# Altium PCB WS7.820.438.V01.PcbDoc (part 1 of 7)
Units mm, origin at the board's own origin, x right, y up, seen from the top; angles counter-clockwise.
Board outline 143.01 x 224 mm, 4 copper layers (Top Layer, G2, S3, Bottom Layer); 863 components, 638 nets, 2623 pads, 4664 vias.
Unrouted connection lines stored in the file: 16.
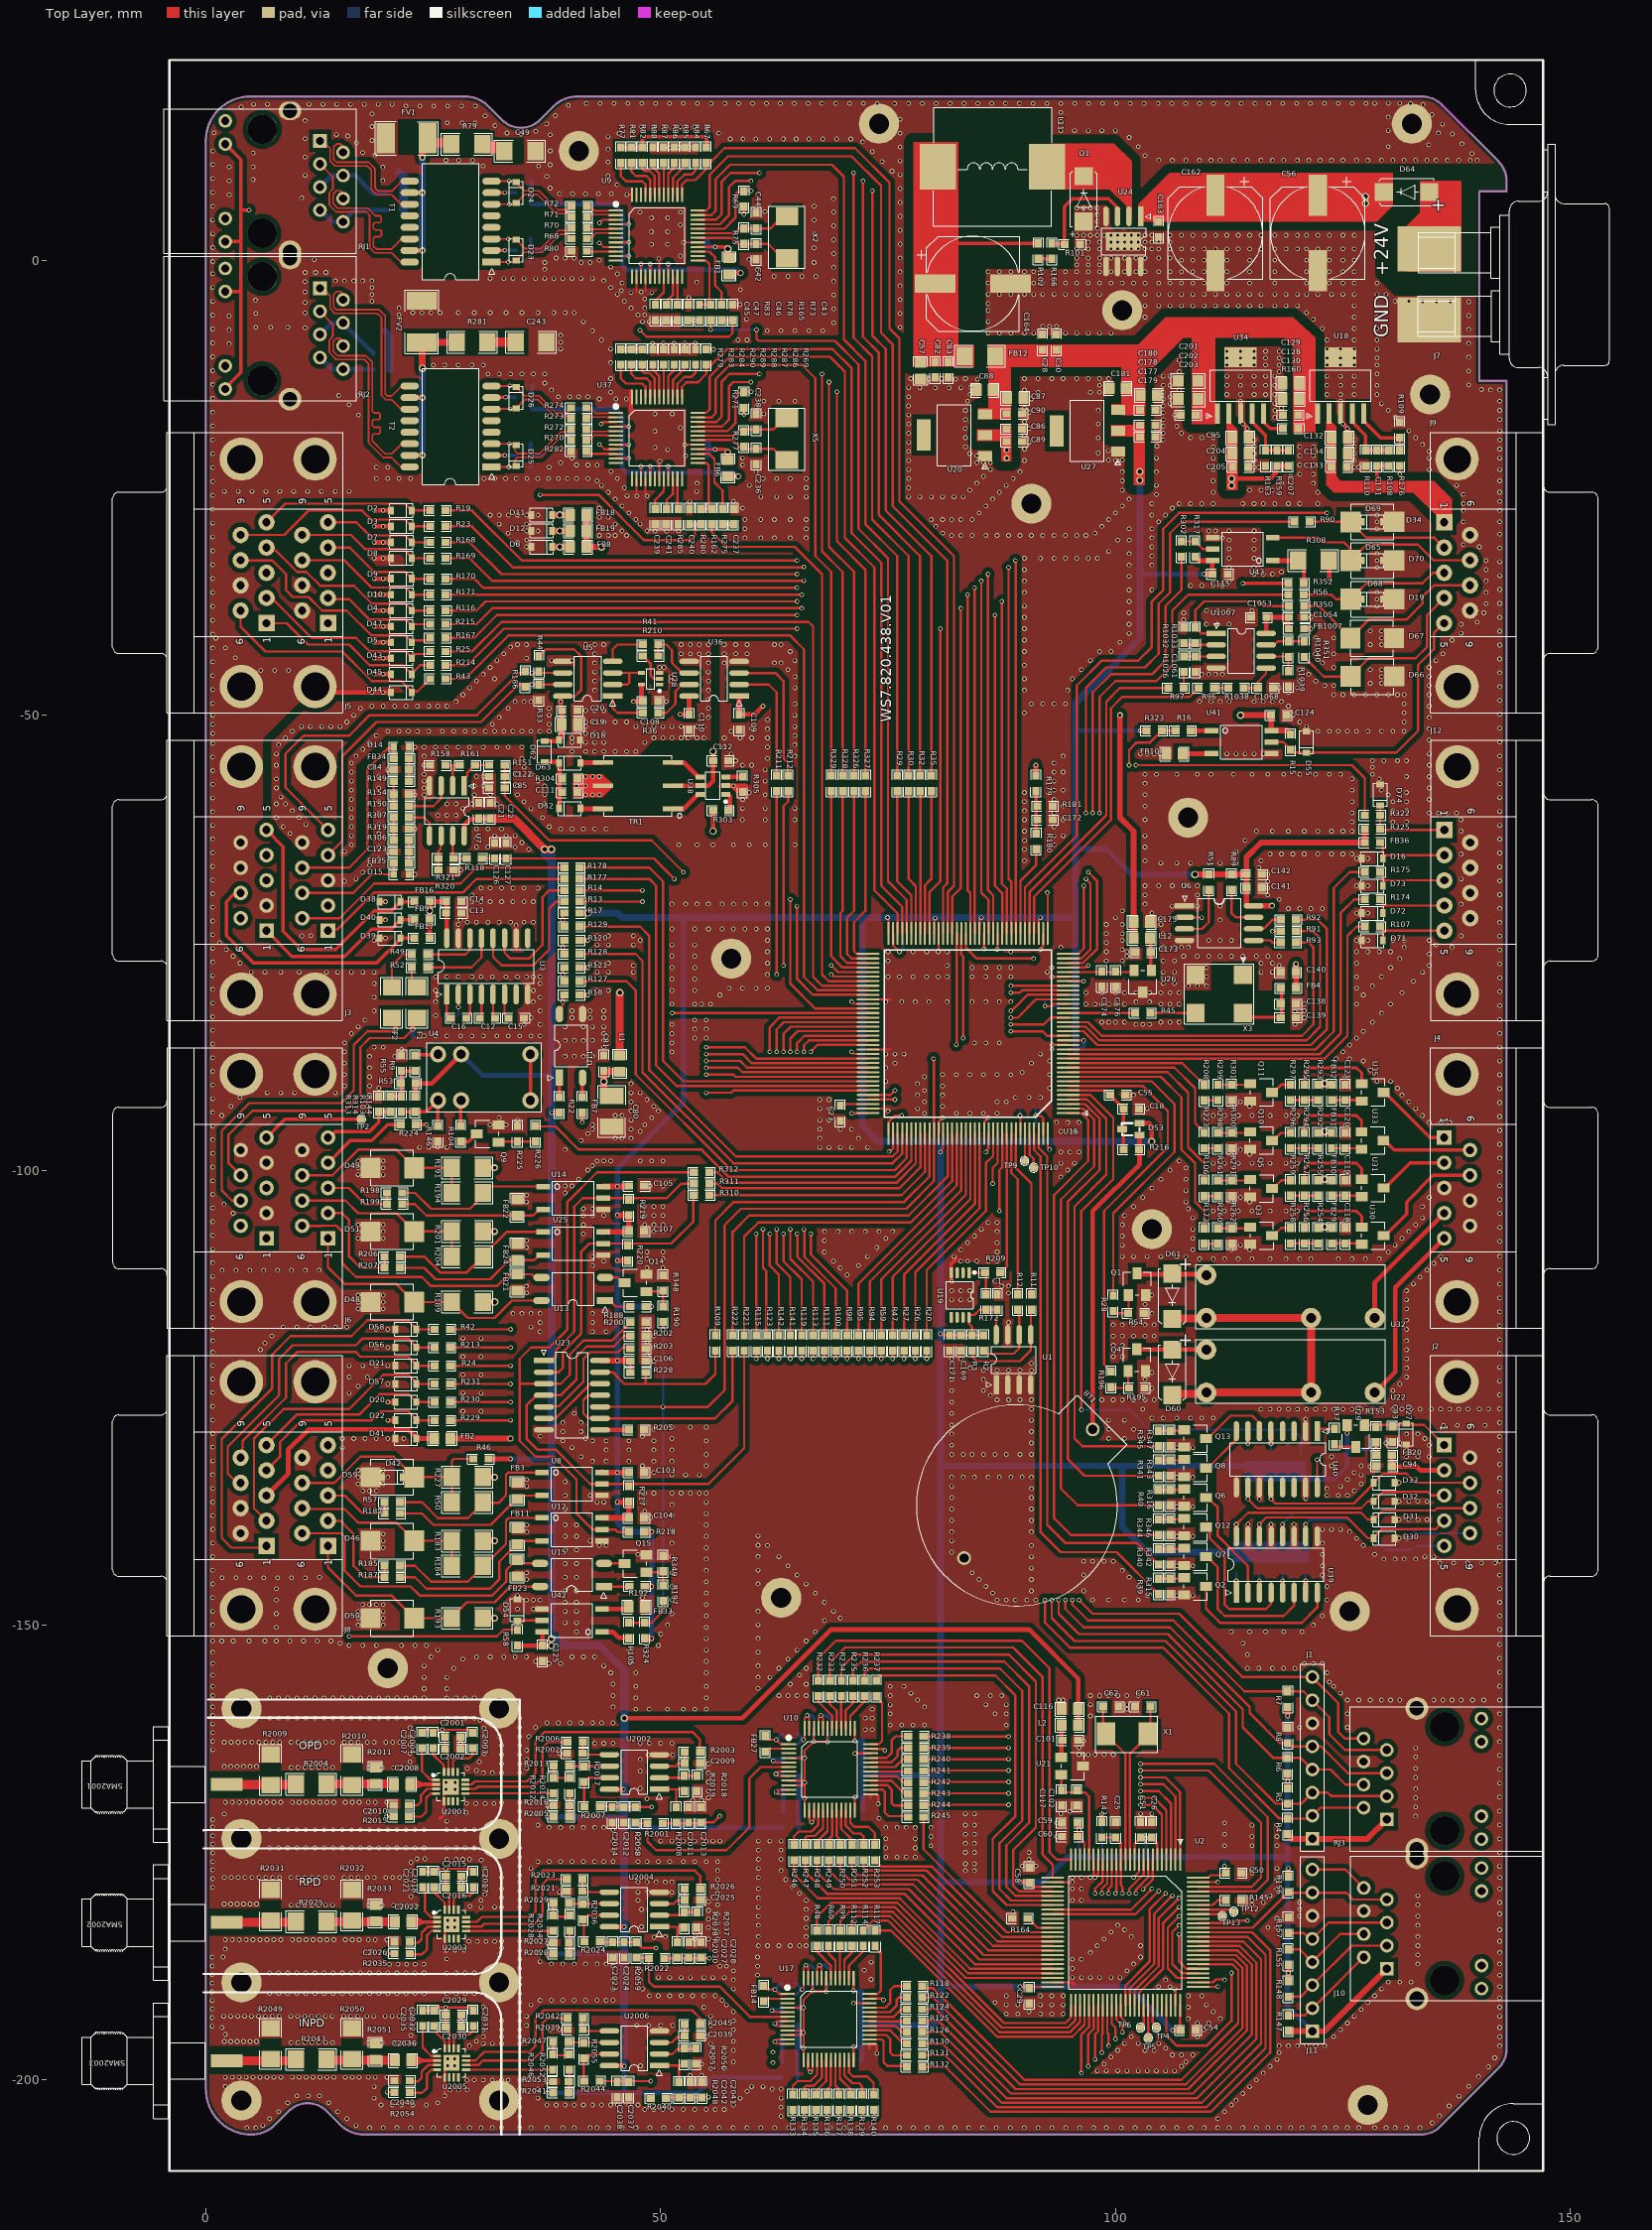
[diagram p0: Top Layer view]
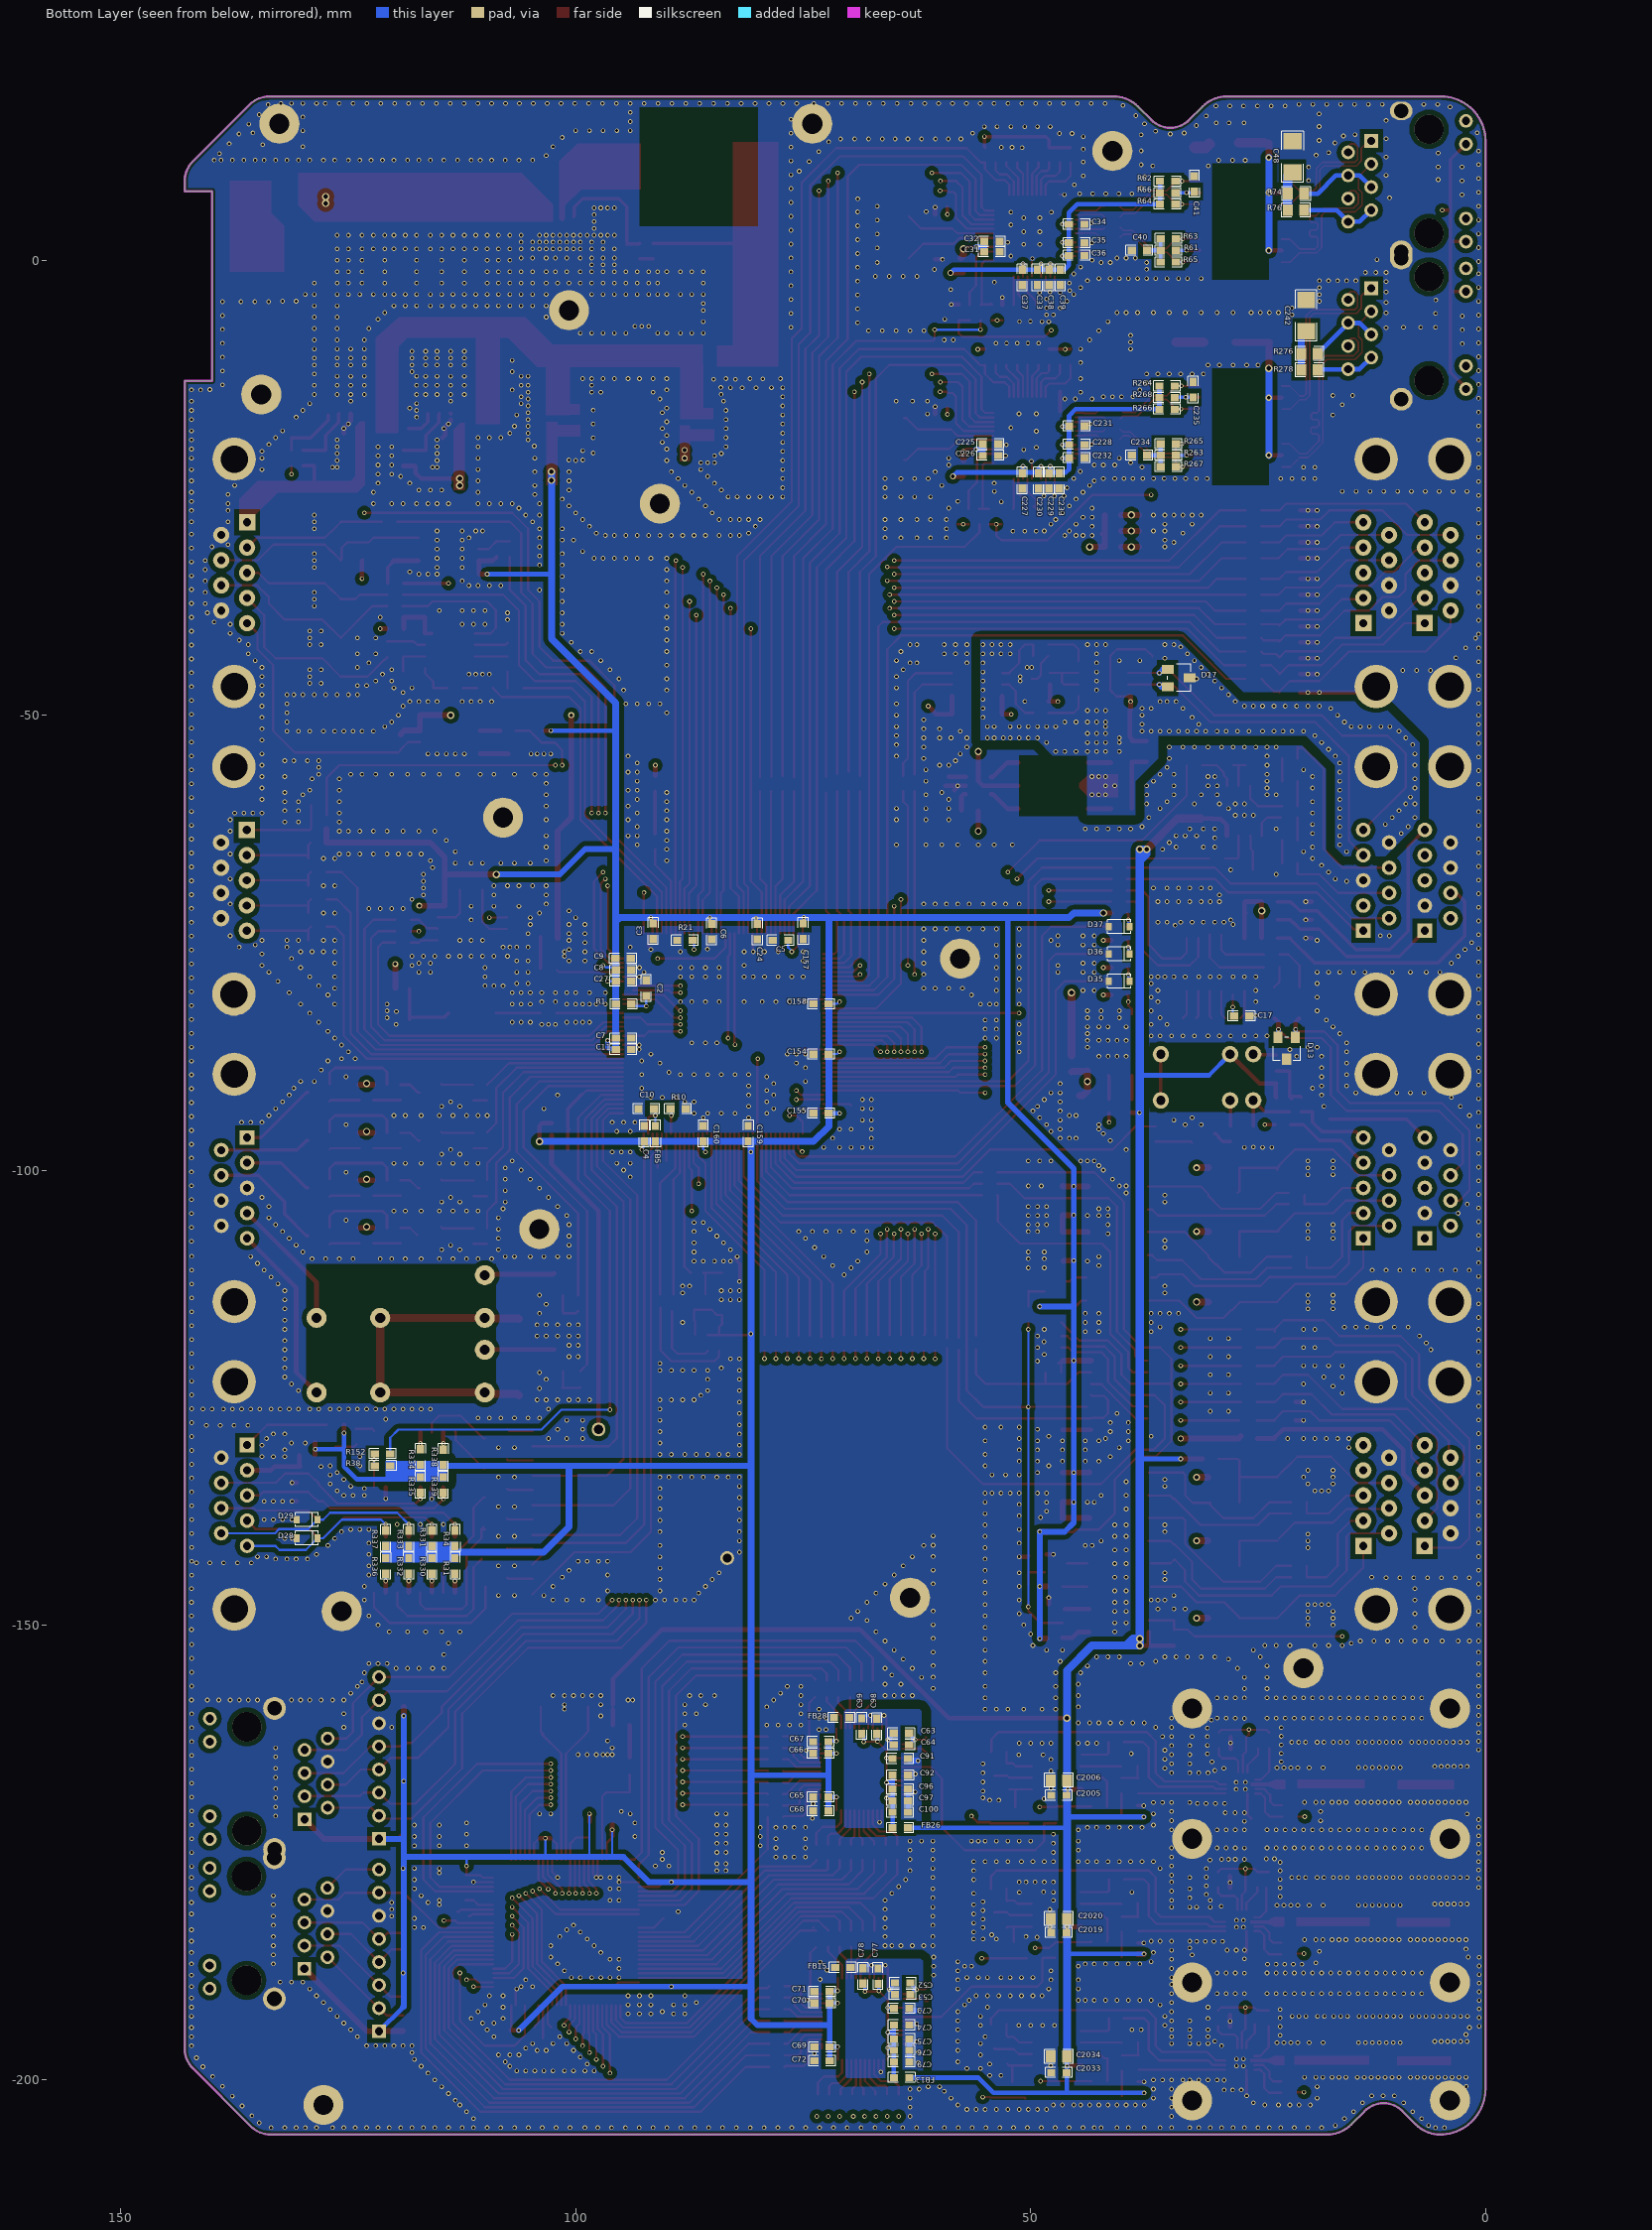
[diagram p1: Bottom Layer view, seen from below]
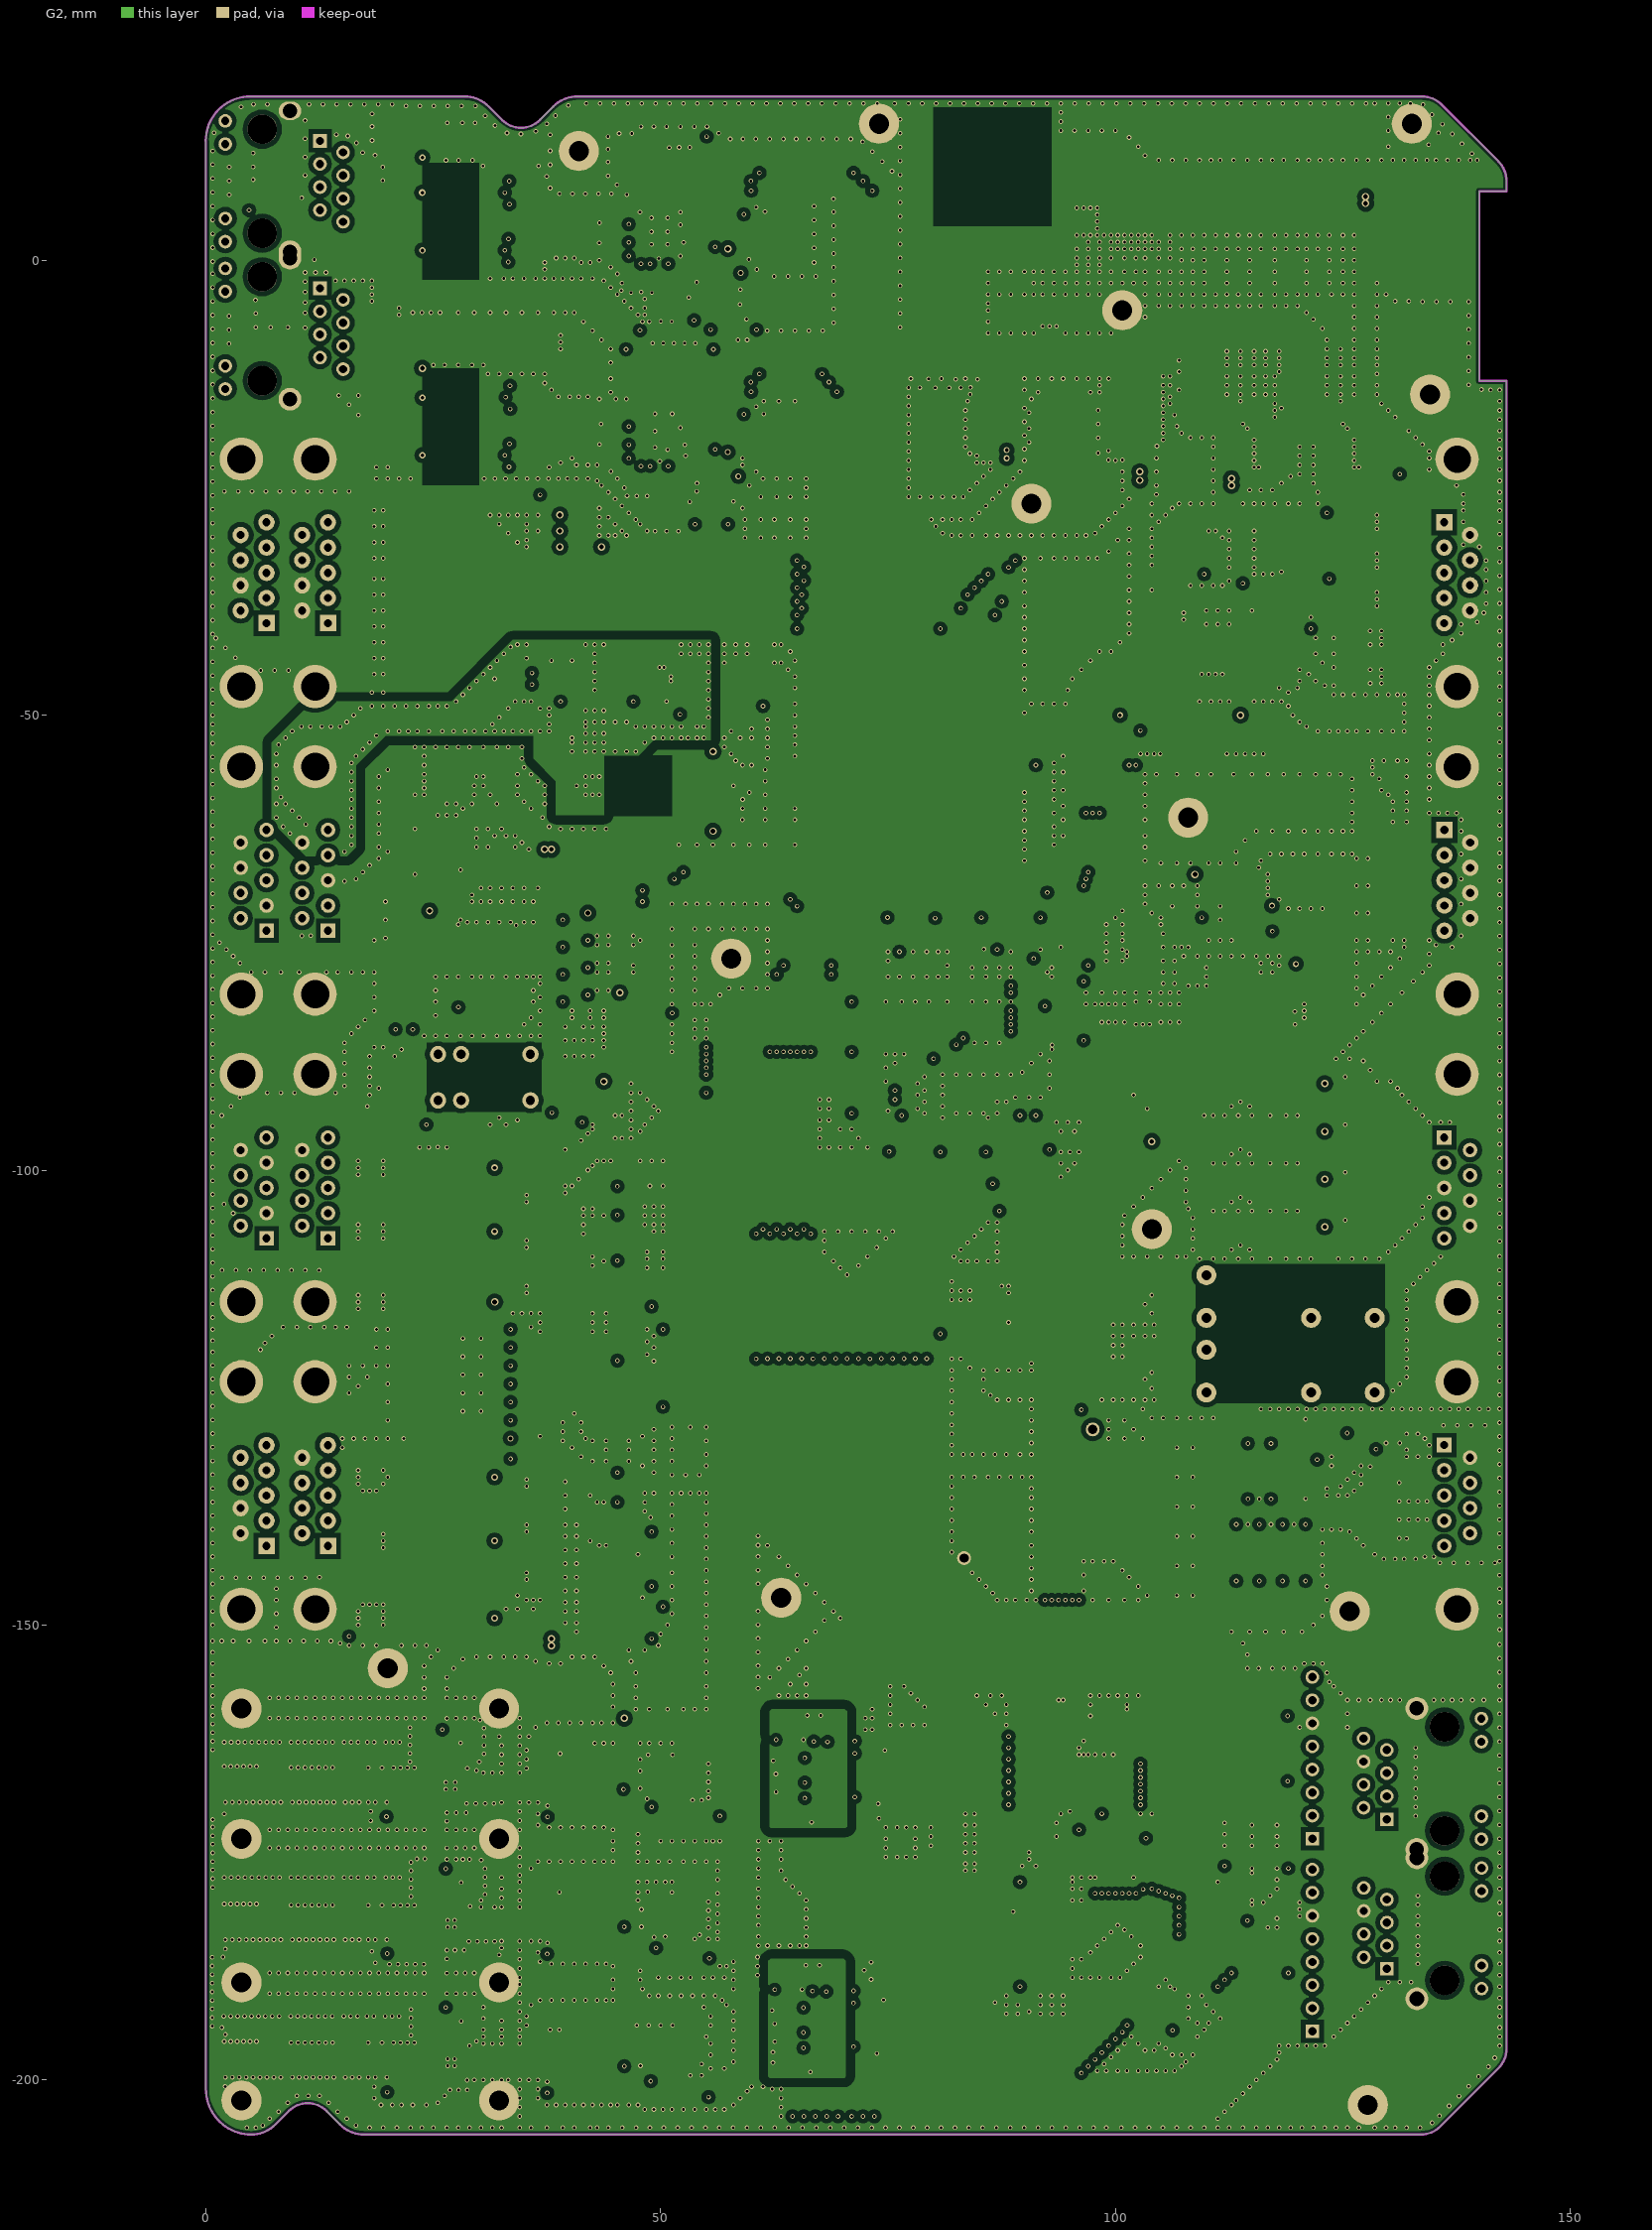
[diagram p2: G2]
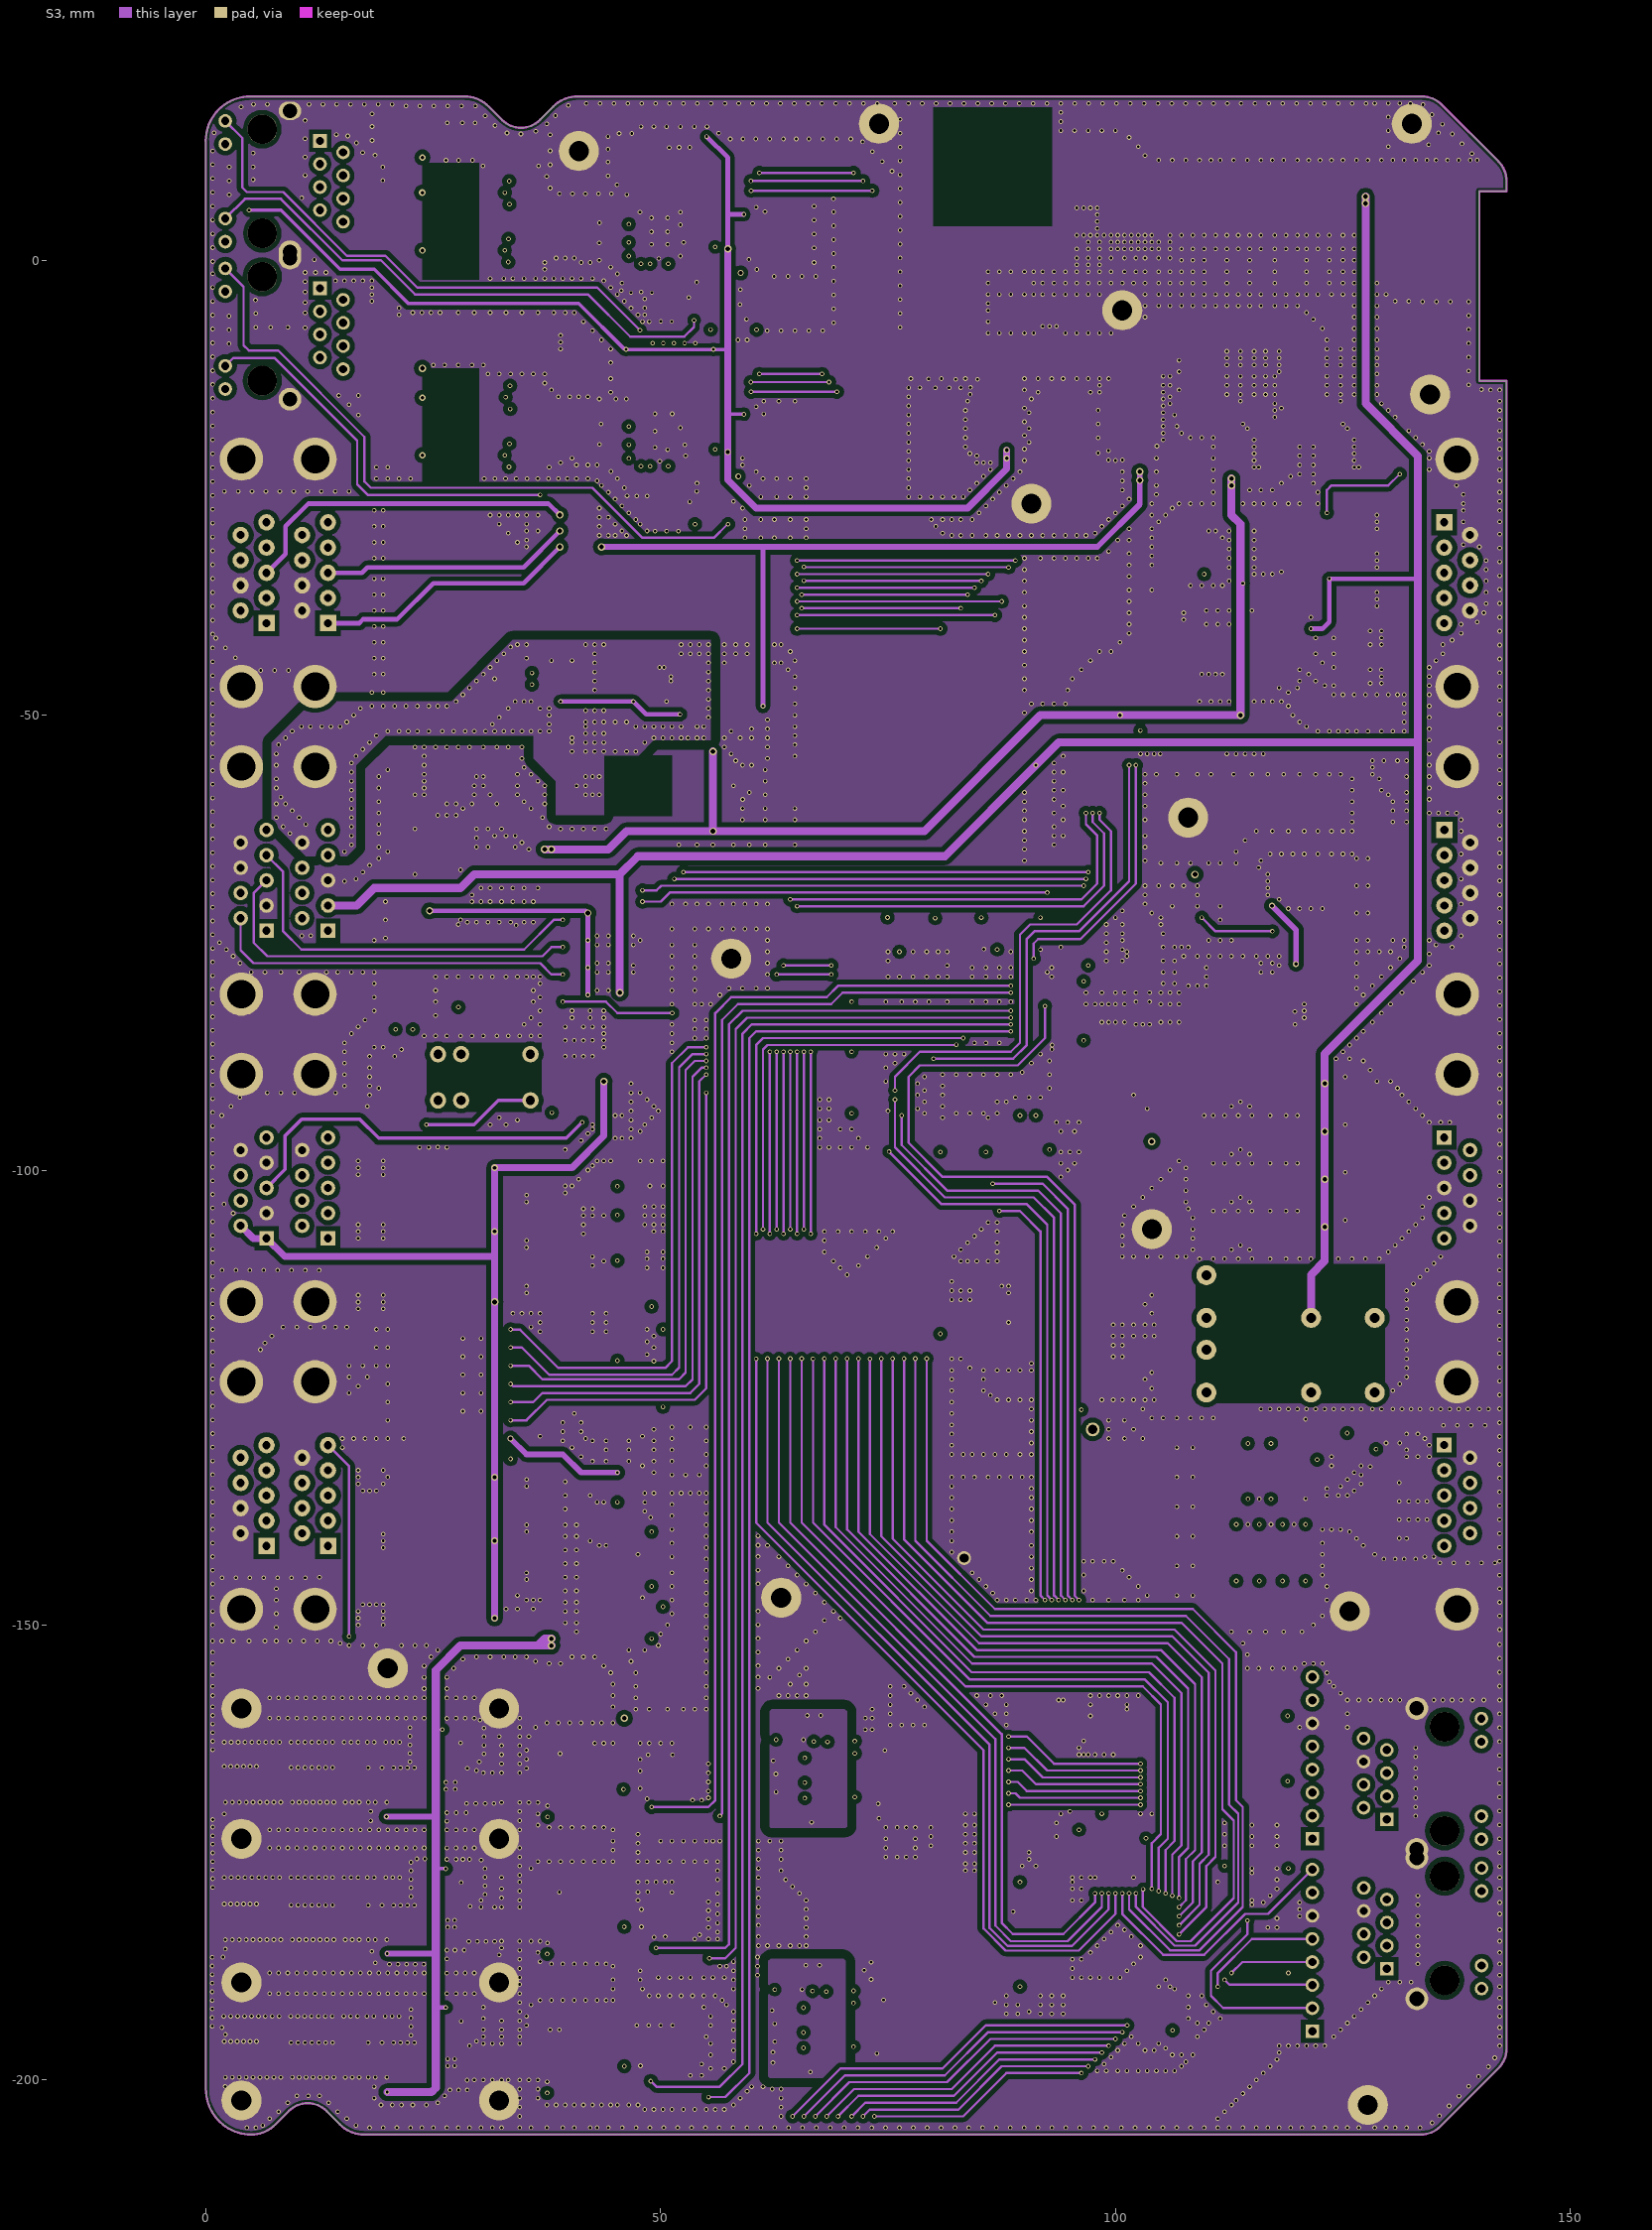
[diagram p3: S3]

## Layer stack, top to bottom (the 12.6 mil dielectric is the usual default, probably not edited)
Top Solder: solder mask 0.0102, Solder Resist, Dk 3.5
Top Layer: signal copper 0.0356
Dielectric1: core 0.32, FR-4, Dk 4.8
G2: signal copper 0.0356
Dielectric3: prepreg 0.32, FR-4, Dk 4.8
S3: signal copper 0.0356
Dielectric2: core 0.32, FR-4, Dk 4.8
Bottom Layer: signal copper 0.0356
Bottom Solder: solder mask 0.0102, Solder Resist, Dk 3.5

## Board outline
5,-206 ccw(c4.998,-202.28) 7.63,-204.909 9.113,-203.426 cw(c11.194,-205.508) 11.194,-202.564 cw(c11.194,-205.508) 13.276,-203.426 14.759,-204.909 ccw(c17.392,-202.276) 17.392,-206 133.557,-206 ccw(c133.557,-202.934) 135.725,-205.102 142.102,-198.725 ccw(c139.934,-196.557) 143,-196.557 143,-13.245 140,-13.245 140,7.583 143,7.583 143,8.697 ccw(c139.934,8.697) 142.102,10.865 135.865,17.102 ccw(c133.697,14.934) 133.697,18 40.752,18 40.843,18 ccw(c40.843,14.276) 38.21,16.909 36.727,15.426 cw(c34.646,17.508) 34.646,14.564 cw(c34.646,17.508) 32.564,15.426 31.081,16.909 ccw(c28.448,14.276) 28.448,18 4.864,18 ccw(c4.864,13.127) -0.008,13.127 0,13.127 0,-200.981 0,-201 ccw(c5,-201)

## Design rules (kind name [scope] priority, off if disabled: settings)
Clearance Clearance_4 [(OnLayer('Keep-Out Layer'))] p1: gap=0.254 ignorepadtopadclearanceinfootprint=FALSE except(0: Arc-Hole Track-Hole SMDPad-Hole THPad-Hole Via-Hole Fill-Hole Poly-Hole Region-Hole Text-Hole)
Clearance Clearance_2 [IsFill vs (InPolygon)] p2: gap=1.016 ignorepadtopadclearanceinfootprint=FALSE except(0: Arc-Hole Track-Hole SMDPad-Hole THPad-Hole Via-Hole Fill-Hole Poly-Hole Region-Hole Text-Hole)
Clearance Clearance_1 [All vs (InPolygon)] p3: gap=0.508 ignorepadtopadclearanceinfootprint=FALSE except(0: Arc-Hole Track-Hole SMDPad-Hole THPad-Hole Via-Hole Fill-Hole Poly-Hole Region-Hole Text-Hole; 1: Fill-Fill Fill-Poly Fill-Region Poly-Poly Poly-Region Region-Region)
Clearance [All] p4: gap=0.152 ignorepadtopadclearanceinfootprint=FALSE except(0: Arc-Hole Track-Hole SMDPad-Hole THPad-Hole Via-Hole Fill-Hole Poly-Hole Region-Hole Text-Hole)
ComponentClearance [All] p1: gap=0 collisioncheckmode=3 verticalgap=0 showdistances=FALSE
DiffPairsRouting DP1DiffPairsRouting [InDifferentialPair ('D01') Or InDifferentialPair ('ADC_D1011') Or InDifferentialPair ('D1213') Or InDifferentialPair ('W5500_TX2') Or InDifferentialPair ('D67') Or InDifferentialPair ('ADC_D1213') Or InDifferentialPair ('D89') Or InDifferentialPair ('TX12') Or InDifferentialPair ('D1011') Or InDifferentialPair ('ADC_DCO') Or InDifferentialPair ('ADC_D89') Or InDifferentialPair ('D23') Or InDifferentialPair ('D45') Or InDifferentialPair ('ADC_D23') Or InDifferentialPair ('ADC_D67') Or InDifferentialPair ('ADC_D01') Or InDifferentialPair ('ADC_D45') Or InDifferentialPair ('W5500_RX2') Or InDifferentialPair ('RX') Or InDifferentialPair ('RX12') Or InDifferentialPair ('W5500_RX1') Or InDifferentialPair ('TX2') Or InDifferentialPair ('TX1') Or InDifferentialPair ('RX1') Or InDifferentialPair ('RX2') Or InDifferentialPair ('TX') Or InDifferentialPair ('W5500_TX1') Or InDifferentialPair ('DAC_IOUT') Or InDifferentialPair ('OUT') Or InDifferentialPair ('DCO') Or InDifferentialPair ('ADC_CLK') Or InDifferentialPair ('VIN')] p1: maxlimit=0.508 minlimit=0.216 mostfreqgap=0.216 toplayer_minwidth=0.381 toplayer_maxwidth=0.381 toplayer_prefwidth=0.381 midlayer1_minwidth=0.381 midlayer1_maxwidth=0.381 midlayer1_prefwidth=0.381 midlayer2_minwidth=0.381 midlayer2_maxwidth=0.381 midlayer2_prefwidth=0.381 bottomlayer_minwidth=0.381 bottomlayer_maxwidth=0.381 bottomlayer_prefwidth=0.381 maxuncoupledlength=12.7
HoleSize [All] p1: absolutevalues=TRUE maxlimit=10 minlimit=0.025 maxpercent=80.000 minpercent=20.000
HoleToHoleClearance [All] p1: gap=0 allowstackedmicrovias=TRUE
MatchedLengths DP1MatchedLengths [InDifferentialPair ('D01') Or InDifferentialPair ('ADC_D1011') Or InDifferentialPair ('D1213') Or InDifferentialPair ('W5500_TX2') Or InDifferentialPair ('D67') Or InDifferentialPair ('ADC_D1213') Or InDifferentialPair ('D89') Or InDifferentialPair ('TX12') Or InDifferentialPair ('D1011') Or InDifferentialPair ('ADC_DCO') Or InDifferentialPair ('ADC_D89') Or InDifferentialPair ('D23') Or InDifferentialPair ('D45') Or InDifferentialPair ('ADC_D23') Or InDifferentialPair ('ADC_D67') Or InDifferentialPair ('ADC_D01') Or InDifferentialPair ('ADC_D45') Or InDifferentialPair ('W5500_RX2') Or InDifferentialPair ('RX') Or InDifferentialPair ('RX12') Or InDifferentialPair ('W5500_RX1') Or InDifferentialPair ('TX2') Or InDifferentialPair ('TX1') Or InDifferentialPair ('RX1') Or InDifferentialPair ('RX2') Or InDifferentialPair ('TX') Or InDifferentialPair ('W5500_TX1') Or InDifferentialPair ('DAC_IOUT') Or InDifferentialPair ('OUT') Or InDifferentialPair ('DCO') Or InDifferentialPair ('ADC_CLK') Or InDifferentialPair ('VIN')] p1 off: tolerance=5.08 checknetsindiffpair=TRUE checkdiffpairvsdiffpair=FALSE checkxsignals=FALSE checkothers=FALSE
MinimumSolderMaskSliver [All] p1: minsoldermaskwidth=0
PlaneConnect [All] p1: planeconnectstyle=Direct reliefexpansion=0.508 reliefentries=4 reliefconductorwidth=0.508 reliefairgap=0.254
PolygonConnect [All] p1: connectstyle=Direct reliefconductorwidth=0.508 reliefentries=4 polygonreliefangle="45 Angle" airgapwidth=0.254
RoutingVias [All] p1: holewidth=0.305 width=0.508 viastyle="Through Hole" minholewidth=0.305 minwidth=0.508 maxholewidth=0.711 maxwidth=1.27
SilkToSilkClearance [All] p1: silktosilkclearance=0
SilkToSolderMaskClearance SilkscreenOverComponentPads [IsPad] p1: minsilkscreentomaskgap=0 clearancetoexposedcopper=TRUE
SolderMaskExpansion [All] p1: expansion=0 istentingtop=FALSE
Width DP1Width [InDifferentialPair('D01') Or InDifferentialPair('ADC_D1011') Or InDifferentialPair('D1213') Or InDifferentialPair('W5500_TX2') Or InDifferentialPair('D67') Or InDifferentialPair('ADC_D1213') Or InDifferentialPair('D89') Or InDifferentialPair('TX12') Or InDifferentialPair('D1011') Or InDifferentialPair('ADC_DCO') Or InDifferentialPair('ADC_D89') Or InDifferentialPair('D23') Or InDifferentialPair('D45') Or InDifferentialPair('ADC_D23') Or InDifferentialPair('ADC_D67') Or InDifferentialPair('ADC_D01') Or InDifferentialPair('ADC_D45') Or InDifferentialPair('W5500_RX2') Or InDifferentialPair('RX') Or InDifferentialPair('RX12') Or InDifferentialPair('W5500_RX1') Or InDifferentialPair('TX2') Or InDifferentialPair('TX1') Or InDifferentialPair('RX1') Or InDifferentialPair('RX2') Or InDifferentialPair('TX') Or InDifferentialPair('W5500_TX1') Or InDifferentialPair('DAC_IOUT') Or InDifferentialPair('OUT') Or InDifferentialPair('DCO') Or InDifferentialPair('ADC_CLK') Or InDifferentialPair('VIN')] p1: maxlimit=0.191 minlimit=0.191 preferedwidth=0.191
Width [All] p2: maxlimit=5.08 minlimit=0.191 preferedwidth=0.191
22 further rules are at their usual default settings.

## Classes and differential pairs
component class 3-ADC: C25 C26 C29 C50 C51 C52 C53 C54 C58 C59 C60 C61 C62 C63 C64 C65 C66 C67 C68 C69 C70 C71 C72 C73 C74 C75 C76 C77 C78 C79 C91 C92 C96 C97 C98 C99 C100 C152 C153 C156 C185 C211 C256 C257 C258 C259 C260 C261 C262 C263 C264 C265 C276 C323 C324 C325 C326 C327 FB13 FB14 FB15 FB26 FB27 FB28 J10 J11 R48 R60 R99 R112 R114 R117 R118 R122 R124 R125 R126 R130 R131 R132 R133 R134 R135 R136 R137 R138 R139 R140 R143 R145 R147 R148 R155 R156 R157 R164 R232 R233 R234 R235 R236 R237 R238 R239 R240 R241 R242 R243 R244 R245 R246 R247 R248 R249 R250 R251 R252 R253 R367 R368 R369 R371 R372 R373 R374 R375 R376 R377 R378 R379 SMA3 TP4 TP5 TP6 TP12 TP13 TP? U2 U10 U17 X1
component class 5-POWER: C5? C28 C30 C56 C57 C82 C83 C86 C87 C88 C89 C90 C95 C101 C102 C116 C117 C118 C119 C120 C121 C128 C129 C130 C131 C132 C133 C134 C162 C163 C164 C172 C173 C174 C175 C176 C177 C178 C179 C180 C181 C201 C202 C203 C204 C205 C207 D1 D60 D61 D64 FB12 FB29 FB30 FB31 FB32 J7 L2 L11 L12 Q1 Q3 Q4 Q5 Q10 Q11 R28 R54 R101 R102 R108 R109 R110 R159 R160 R163 R166 R179 R180 R181 R195 R196 R254 R255 R256 R257 R258 R259 R260 R261 R262 R291 R292 R293 R294 R295 R296 R297 R298 R299 R300 R301 U18 U20 U21 U22 U24 U26 U27 U30 U31 U32 U33 U34 U35
component class 2-RJ45: C31 C32 C33 C34 C35 C36 C37 C38 C39 C40 C41 C42 C43 C44 C45 C46 C47 C48 C49 C225 C226 C227 C228 C229 C230 C231 C232 C233 C234 C235 C236 C237 C238 C239 C240 C241 C242 C243 D23 D24 D25 D26 FB1 FB6 FV1 FV2 R61 R62 R63 R64 R65 R66 R67 R68 R69 R70 R71 R72 R73 R74 R75 R76 R77 R78 R79 R80 R81 R82 R83 R84 R85 R86 R87 R88 R263 R264 R265 R266 R267 R268 R269 R270 R271 R272 R273 R274 R275 R276 R277 R278 R279 R280 R281 R282 R283 R284 R285 R286 R287 R288 R289 R290 RJ1 RJ2 T1 T2 U9 U37 X2 X5
component class 1-MCU: BT1 C1 C2 C3 C4 C5 C6 C7 C8 C9 C10 C11 C12 C13 C14 C15 C16 C17 C18 C19 C20 C21 C22 C23 C24 C27 C55 C80 C81 C84 C85 C93 C94 C103 C104 C105 C106 C107 C108 C109 C110 C111 C112 C115 C122 C123 C124 C125 C126 C127 C138 C139 C140 C141 C142 C154 C155 C157 C158 C159 C160 C169 C171 C1053 C1054 C1061 C1068 D2 D3 D4 D5 D6 D7 D8 D9 D10 D11 D12 D13 D14 D15 D16 D17 D18 D19 D20 D21 D22 D27 D28 D29 D30 D31 D32 D33 D34 D35 D36 D37 D38 D39 D40 D41 D42 D43 D44 D45 D46 D47 D48 D49 D50 D51 D52 D53 D54 D55 D56 D57 D58 D59 D62 D63 D65 D66 D67 D68 D69 D70 D71 D72 D73 D74 F1 F2 FB2 FB3 FB4 FB5 FB7 FB8 FB9 FB10 FB11 FB16 FB17 FB18 FB19 FB20 FB21 FB22 FB23 FB24 FB33 FB34 FB35 FB36 FB1007 J1 J2 J3 J4 J5 J6 J8 J9 J12 L1 Q2 Q6 Q7 Q8 Q9 Q12 Q13 Q14 Q15 R1 R2 R3 R4 R5 R6 R7 R8 R9 R10 R11 R12 R13 R14 R15 R16 R17 R18 R19 R20 R21 R22 R23 R24 R25 R26 R27 R29 R30 R31 R32 R33 R34 R35 R36 R37 R38 R39 R40 R41 R42 R43 R44 R45 R46 R47 R49 R50 R51 R52 R53 R55 R56 R57 R58 R59 R89 R90 R91 R92 R93 R94 R95 R96 R97 R98 R100 R103 R104 R105 R106 R107 R111 R113 R115 R116 R119 R120 R121 R123 R127 R128 R129 R141 R142 R144 R146 R149 R150 R151 R152 R153 R154 R158 R161 R162 R165 R167 R168 R169 R170 R171 R172 R173 R174 R175 R176 R177 R178 R182 R183 R184 R185 R186 R187 R188 R189 R190 R191 R192 R193 R194 R197 R198 R199 R200 R201 R202 R203 R204 R205 R206 R207 R208 R209 R210 R211 R212 R213 R214 R215 R216 R217 R218 R219 R220 R221 R222 R223 R224 R225 R226 R227 R228 R229 R230 R231 R302 R303 R304 R305 R306 R307 R308 R309 R310 R311 R312 R313 R314 R315 R316 R317 R318 R319 R320 R321 R322 R323 R324 R325 R326 R327 R328 R329 R330 R331 R332 R333 R334 R335 R336 R337 R338 R339 R340 R341 R342 R343 R344 R345 R346 R347 R348 R349 R350 R351 R352 R1026 R1032 R1033 R1038 R1039 R1040 RJ3 TP2 TP9 TP10 TR1 U1 U3 U4 U5 U6 U7 U8 U11 U12 U13 U14 U15 U16 U19 U23 U25 U28 U29 U36 U38 U39 U40 U41 U42 U43 U1007 X3
component class 4-RF-PD: C2001 C2002 C2003 C2004 C2005 C2006 C2007 C2008 C2009 C2010 C2011 C2012 C2013 C2014 C2015 C2016 C2017 C2018 C2019 C2020 C2021 C2022 C2023 C2024 C2025 C2026 C2027 C2028 C2029 C2030 C2031 C2032 C2033 C2034 C2035 C2036 C2037 C2038 C2039 C2040 C2041 C2042 R2001 R2002 R2003 R2004 R2005 R2006 R2007 R2008 R2009 R2010 R2011 R2012 R2013 R2014 R2015 R2016 R2017 R2018 R2019 R2020 R2021 R2022 R2023 R2024 R2025 R2026 R2027 R2028 R2029 R2030 R2031 R2032 R2033 R2034 R2035 R2036 R2037 R2038 R2039 R2040 R2041 R2042 R2043 R2044 R2045 R2046 R2047 R2048 R2049 R2050 R2051 R2052 R2053 R2054 R2055 R2056 R2057 R2058 R2059 SMA2001 SMA2002 SMA2003 U2001 U2002 U2003 U2004 U2005 U2006
differential pair W5500_TX2: +W5500_TX2_P -W5500_TX2_N
differential pair W5500_RX2: +W5500_RX2_P -W5500_RX2_N
differential pair TX12: +TX12_P -TX12_N
differential pair TX2: +TX2_P -TX2_N
differential pair RX12: +RX12_P -RX12_N
differential pair RX2: +RX2_P -RX2_N
differential pair W5500_TX1: +W5500_TX1_P -W5500_TX1_N
differential pair W5500_RX1: +W5500_RX1_P -W5500_RX1_N
differential pair TX: +TX_P -TX_N
differential pair TX1: +TX1_P -TX1_N
differential pair RX: +RX_P -RX_N
differential pair RX1: +RX1_P -RX1_N

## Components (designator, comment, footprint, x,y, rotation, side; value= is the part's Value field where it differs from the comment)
BT1 "Battery" CR2032 90.429,-135.571 r45 top locked
C1 "0.1uF" C0603#1 87,-114.5 r270 top
C2 "0.1uF" C0603#1 92.25,-80 r270 bottom
C3 "0.1uF" C0603#1 91.5,-73.75 r90 bottom
C4 "0.1uF" C0603#1 92.5,-96 r270 bottom
C5 "0.1uF" C0603#1 80.051,-73.787 r90 bottom
C6 "0.1uF" C0603#1 85.051,-73.787 r90 bottom
C7 "0.1uF" C0603#1 94.75,-85.5 r0 bottom
C8 "0.1uF" C0603#1 94.75,-78 r0 bottom
C9 "10uF/6.3V" C0603#1 94.801,-76.737 r0 bottom
C10 "0.1uF" C0603#1 92.25,-93.25 r0 bottom
C11 "10uF/6.3V" C0603#1 94.75,-86.75 r0 bottom
C12 "0.1uF" C0603#1 30.95,-83.303 r0 top
C13 "0.1uF" C0603#1 27.25,-71.75 r180 top
C14 "1uF" C0603#1 27.25,-70.5 r0 top
C15 "0.1uF" C0603#1 34.125,-83.303 r0 top
C16 "0.1uF" C0603#1 27.775,-83.303 r0 top
C17 "0.1uF" C0603#1 26.797,-83.058 r180 bottom
C18 "0.1uF" C0603#2 101.75,-93.25 r0 top
C19 "10uF/10V" C0805#1 40,-51 r180 top
C20 "0.1uF" C0603#1 40,-49.5 r180 top
C21 "0.1uF" C0603#2 30,-60.5 r90 top
C22 "2.2UF" C0603#1 31.25,-60.5 r90 top
C23 "2.2uF" C0603#2 69.75,-93.75 r270 top
C24 "2.2uF" C0603#2 77.5,-74.75 r180 bottom
C25 "0.1uF" C0603#1 100,-172.5 r270 top
C26 "0.1uF" C0603#1 104,-172.5 r270 top
C27 "0.1uF" C0603#2 94.75,-79.25 r180 bottom
C28 "1nF" C0603#2 92,-9 r90 top
C29 "0.1uF" C0603#2 90.5,-190.75 r270 top
C30 "0.1uF" C0603#2 93.5,-9 r90 top
C31 "0.1uF" C0603#1 54.252,0.917 r0 bottom
C32 "10uF/6.3V" C0603#1 54.252,2.09 r0 bottom
C33 "0.1uF" C0603#1 49.256,-1.89 r90 bottom
C34 "0.1uF" C0603#1 44.938,3.952 r0 bottom
C35 "0.1uF" C0603#1 44.938,1.92 r0 bottom
C36 "0.1uF" C0603#1 44.938,0.523 r0 bottom
C37 "0.1uF" C0603#1 50.907,-1.89 r90 bottom
C38 "0.1uF" C0603#1 47.986,-1.89 r90 bottom
C39 "10uF/6.3V" C0603#1 46.716,-1.89 r90 bottom
C40 "10nF" C0603#1 38.029,1.092 r180 bottom
C41 "22nF" C0603#1 32.004,8.382 r270 bottom
C42 "18pF" C0603#1 60.496,0.947 r90 top
C43 "1nF" C0603#1 57.905,-5.745 r270 top
C44 "18pF" C0603#1 60.496,4.351 r270 top
C45 "4.7uF/6.3V" C0603#1 49.414,-5.745 r90 top
C46 "1nF" C0603#1 53.053,-5.745 r270 top
C47 "10nF" C0603#1 50.627,-5.745 r270 top
C48 "1nF/2KV" C1206 21.209,11.375 r270 bottom
C49 "1nF/2KV" C1206 34.532,12.007 r180 top
C50 "0.1uF" C0603#2 113,-177.25 r0 top
C51 "0.1uF" C0603#1 102.75,-172.5 r270 top
C52 "0.1uF" C0603#2 64.072,-189.336 r180 bottom
C53 "10uF/6.3V" C0603#2 64.072,-190.606 r180 bottom
C54 "0.1uF" C0603#2 108,-194.55 r0 top
C55 "10uF/6.3V" C0603#2 100.25,-91.75 r0 top
C56 "100uF/63V" ECAP2SM_10R4x10R4 122.25,3 r270 top
C57 "10uF/10V" C0805#1 78.566,-12.136 r270 top
C58 "0.1uF" C0603#2 90.5,-177.5 r90 top
C59 "0.1uF" C0603#2 95,-171.75 r180 top
C60 "10uF/6.3V" C0603#2 95,-173.25 r180 top
C61 "20pF" C0603#2 103,-159 r0 top
C62 "20pF" C0603#1 99.5,-159 r0 top
C63 "0.1uF" C0603#1 64.212,-161.886 r0 bottom
C64 "10uF/6.3V" C0603#1 64.212,-163.156 r0 bottom
C65 "0.1uF" C0603#1 73.066,-168.928 r180 bottom
C66 "0.1uF" C0603#2 73.066,-164.102 r0 bottom
C67 "0.1uF" C0603#2 73.066,-162.832 r0 bottom
C68 "10uF/6.3V" C0603#1 73.066,-170.452 r180 bottom
C69 "0.1uF" C0603#2 72.926,-196.378 r0 bottom
C70 "0.1uF" C0603#2 72.926,-191.552 r0 bottom
C71 "0.1uF" C0603#2 72.926,-190.282 r0 bottom
C72 "10uF/6.3V" C0603#2 72.926,-197.902 r0 bottom
C73 "0.1uF" C0603#2 64.182,-192.13 r180 bottom
C74 "0.1uF" C0603#2 64.182,-193.968 r180 bottom
C75 "0.1uF" C0603#2 64.182,-195.492 r180 bottom
C76 "0.1uF" C0603#2 64.182,-196.762 r180 bottom
C77 "0.1uF" C0603#2 66.775,-188.591 r90 bottom
C78 "0.1uF" C0603#2 68.426,-188.579 r90 bottom
C79 "10uF/6.3V" C0603#2 64.182,-198.032 r180 bottom
C80 "10uF" C1210 44.617,-93.537 r90 top
C81 "0.1uF" C0603#2 43.75,-88.25 r90 top
C82 "1nF" C0603#2 80.176,-12.034 r90 top
C83 "0.1uF" C0603#2 81.617,-12.034 r90 top
C84 "0.1uF" C0603#2 21.5,-56 r180 top
C85 "0.1uF" C0603#1 32,-58 r0 top
C86 "1uF" C0603#1 88.885,-18.534 r180 top
C87 "10uF/10V" C0805#1 88.987,-15.156 r180 top
C88 "10uF/10V" C0805#1 85.634,-14.267 r0 top
C89 "10uF/6.3V" C0603#2 88.885,-19.931 r0 top
C90 "0.1uF" C0603#1 88.885,-16.883 r180 top
C91 "0.1uF" C0603#1 64.322,-164.68 r0 bottom
C92 "0.1uF" C0603#1 64.322,-166.518 r0 bottom
C93 "0.1uF" C0603#2 130.429,-129.032 r270 top
C94 "0.1uF" C0603#2 129.54,-132.588 r0 top
C95 "10uF/10V" C0805#1 113.75,-19.5 r180 top
C96 "0.1uF" C0603#2 64.322,-168.042 r180 bottom
C97 "0.1uF" C0603#2 64.322,-169.312 r180 bottom
C98 "0.1uF" C0603#2 66.915,-161.141 r90 bottom
C99 "0.1uF" C0603#2 68.566,-161.129 r90 bottom
C100 "10uF/6.3V" C0603#2 64.322,-170.582 r180 bottom
C101 "0.1uF" C0603#2 95.02,-162.67 r0 top
C102 "0.1uF" C0603#2 95.75,-169 r270 top
C103 "0.1uF" C0603#2 47.35,-133.25 r0 top
C104 "0.1uF" C0603#2 47.35,-138.25 r0 top
C105 "0.1uF" C0603#2 47.35,-101.75 r0 top
C106 "0.1uF" C0603#2 47.5,-121 r0 top
C107 "0.1uF" C0603#2 47.35,-106.75 r0 top
C108 "0.1uF" C0603#2 48.882,-48.5 r0 top
C109 "0.1uF" C0603#2 58.632,-50.75 r270 top
C110 "0.1uF" C0603#2 53.132,-50.75 r270 top
C111 "4.7UF/16V" C0603#2 40.007,-58.5 r0 top
C112 "1uF" C0603#2 56.607,-55 r0 top
C115 "0.1uF" C0603#2 111.5,-34.5 r0 top
C116 "10uF/10V" C0805#1 95,-159.25 r0 top
C117 "10uF/6.3V" C0603#2 94.077,-169 r270 top
C118 "0.1uF" C0603#2 125.27,-107.21 r90 top
C119 "0.1uF" C0603#2 125.27,-101.96 r90 top
C120 "0.1uF" C0603#2 125.25,-96.75 r90 top
C121 "0.1uF" C0603#2 125.27,-91.46 r90 top
C122 "2.2uF" C0603#2 32,-56.75 r180 top
C123 "0.1uF" C0603#2 21.5,-65 r180 top
C124 "0.1uF" C0603#2 117.95,-50 r0 top
C125 "0.1uF" C0603#2 37,-153.108 r270 top
C126 "0.1uF" C0603#2 31.75,-64.9 r90 top
C127 "2.2uF" C0603#2 33,-64.9 r90 top
C128 "10uF/10V" C0805#1 119.25,-15.25 r0 top
C129 "10uF/10V" C0805#1 119.25,-13.5 r0 top
C130 "0.1uF" C0603#2 119.25,-17 r180 top
C131 "0.1uF" C0603#2 128.75,-21.75 r90 top
C132 "10uF/10V" C0805#1 124.65,-19.5 r180 top
C133 "1uF" C0603#2 124.6,-22.75 r0 top
C134 "10uF/10V" C0805#1 124.65,-21.25 r180 top
C138 "10uF/6.3V" C0603#2 119,-81.75 r0 top
C139 "0.1uF" C0603#2 119,-83.25 r180 top
C140 "0.1uF" C0603#2 119,-78.25 r0 top
C141 "0.1uF" C0603#1 115.25,-69 r180 top
C142 "10uF/6.3V" C0603#1 115.25,-67.5 r180 top
C154 "0.1uF" C0603#2 73.032,-87.249 r0 bottom
C155 "0.1uF" C0603#2 73.032,-93.737 r0 bottom
C157 "0.1uF" C0603#1 75,-73.75 r90 bottom
C158 "0.1uF" C0603#1 73.032,-81.737 r180 bottom
C159 "0.1uF" C0603#1 81.051,-95.987 r270 bottom
C160 "0.1uF" C0603#1 86,-96 r270 bottom
C162 "100uF/63V" ECAP2SM_10R4x10R4 111,3 r270 top
C163 "0.1uF" C0603#2 104.75,3.377 r270 top
C164 "1000uF/16V" ECAP2SM_10R4x10R4 84.319,-2.565 r0 top
C169 "0.1uF" C0603#1 83,-119 r90 top
C171 "10uF/6.3V" C0603#2 81.75,-119 r270 top
C172 "0.1uF" C0603#1 92.25,-61.5 r180 top
C173 "0.1uF" C0603#1 103.036,-76.071 r0 top
C174 "0.1uF" C0603#1 98.5,-79 r90 top
C175 "10uF/10V" C0805#1 102.9,-72.75 r180 top
C176 "10uF/6.3V" C0603#2 100,-79 r270 top
C177 "1uF" C0603#1 103.549,-18.135 r180 top
C178 "0.1uF" C0603#1 103.549,-16.484 r180 top
C179 "10uF/6.3V" C0603#2 103.549,-19.405 r0 top
C180 "10uF/10V" C0805#1 103.651,-14.833 r180 top
C181 "10uF/10V" C0805#1 100.247,-14.071 r0 top
C201 "10uF/10V" C0805#2 108,-13.25 r0 top
C202 "10uF/10V" C0805#2 108,-15.25 r0 top
C203 "0.1uF" C0603#2 108,-17 r180 top
C204 "10uF/10V" C0805#1 113.75,-21.25 r180 top
C205 "1uF" C0603#2 113.75,-22.75 r0 top
C207 "0.1uF" C0603#2 119,-21.75 r90 top
C225 "0.1uF" C0603#2 54.404,-20.186 r180 bottom
C226 "10uF/6.3V" C0603#2 54.404,-21.456 r180 bottom
C227 "0.1uF" C0603#2 50.907,-24.242 r270 bottom
C228 "0.1uF" C0603#2 44.913,-20.254 r180 bottom
C229 "0.1uF" C0603#2 47.986,-24.242 r270 bottom
C230 "0.1uF" C0603#2 49.129,-24.242 r270 bottom
C231 "0.1uF" C0603#2 44.913,-18.222 r180 bottom
C232 "0.1uF" C0603#2 44.913,-21.725 r180 bottom
C233 "10uF/6.3V" C0603#2 46.843,-24.242 r270 bottom
C234 "10nF" C0603#2 38.029,-21.445 r0 bottom
C235 "22nF" C0603#2 32.131,-14.224 r90 bottom
C236 "18pF" C0603#2 60.496,-21.565 r270 top
C237 "1nF" C0603#2 58.007,-28.161 r90 top
C238 "18pF" C0603#2 60.496,-17.755 r90 top
C239 "4.7uF/6.3V" C0603#2 49.383,-28.161 r270 top
C240 "1nF" C0603#2 53.186,-28.161 r90 top
C241 "10nF" C0603#2 50.65,-28.161 r90 top
C242 "1nF/2KV" C1206 19.696,-6.075 r270 bottom
C243 "1nF/2KV" C1206 35.75,-9 r180 top
C1053 "0.1uF" C0603#2 115.75,-39.25 r180 top
C1054 "1uF" C0603#2 119.9,-39.25 r180 top
C1061 "100pF" C0603#2 108.785,-44.392 r270 top
C1068 "100pF" C0603#2 116.5,-47 r0 top
C2001 "0.1uF" C0603#1 27.148,-162.309 r180 top
C2002 "100pF" C0603#1 27.148,-163.613 r0 top
C2003 "0.1uF" C0603#2 29.307,-162.69 r270 top
C2004 "12pF" C0603#2 24.989,-162.69 r270 top
C2005 "0.1uF" C0603#2 46.892,-168.719 r180 bottom
C2006 "10uF/10V" C0805#1 46.892,-167.068 r0 bottom
C2007 "20PF" C0603#2 23.744,-162.69 r90 top
C2008 "100pF" C0805#1 21.585,-167.516 r0 top
C2009 "0.1uF" C0603#2 53.496,-165.196 r0 top
C2010 "open" C0603#2 21.484,-169.802 r180 top
C2011 "0.1uF" C0603#2 53.077,-170.878 r90 top
C2012 "0.1uF" C0603#2 45.934,-170.878 r270 top
C2013 "10uF/6.3V" C0603#2 54.42,-170.878 r90 top
C2014 "1uF" C0603#2 44.664,-170.878 r270 top
C2015 "0.1uF" C0603#1 27.236,-177.601 r180 top
C2016 "100pF" C0603#1 27.236,-178.905 r0 top
C2017 "0.1uF" C0603#2 29.395,-177.982 r270 top
C2018 "12pF" C0603#2 25.077,-177.982 r270 top
C2019 "0.1uF" C0603#2 46.892,-183.812 r180 bottom
C2020 "10uF/10V" C0805#1 46.892,-182.288 r0 bottom
C2021 "20PF" C0603#2 23.832,-177.982 r90 top
C2022 "100pF" C0805#1 21.673,-182.625 r0 top
C2023 "0.1uF" C0603#2 44.714,-185.717 r270 top
C2024 "1uF" C0603#2 45.984,-185.717 r270 top
C2025 "0.1uF" C0603#2 53.496,-180.256 r0 top
C2026 "open" C0603#2 21.571,-184.84 r180 top
C2027 "0.1uF" C0603#2 53.132,-185.717 r90 top
C2028 "10uF/6.3V" C0603#2 54.42,-185.717 r90 top
C2029 "0.1uF" C0603#1 27.236,-192.841 r180 top
C2030 "100pF" C0603#1 27.236,-194.145 r0 top
C2031 "0.1uF" C0603#2 29.395,-193.222 r270 top
C2032 "12pF" C0603#2 25.077,-193.222 r270 top
C2033 "0.1uF" C0603#2 46.892,-199.199 r180 bottom
C2034 "10uF/10V" C0805#1 46.892,-197.421 r0 bottom
C2035 "20PF" C0603#2 23.832,-193.222 r90 top
C2036 "100pF" C0805#1 21.673,-197.865 r0 top
C2037 "0.1uF" C0603#2 46.501,-201.053 r270 top
C2038 "1uF" C0603#2 45.216,-201.053 r270 top
C2039 "0.1uF" C0603#2 53.494,-195.152 r0 top
C2040 "open" C0603#2 21.571,-200.08 r180 top
C2041 "0.1uF" C0603#2 54.5,-201.077 r90 top
C2042 "10uF/6.3V" C0603#2 53.25,-201.077 r90 top
D1 "SS36" DO-214AC 96.5,6.75 r90 top
D2 "ESDLC3V3D3B" SOD-323 21.5,-27.5 r180 top
D3 "ESDLC3V3D3B" SOD-323 21.5,-29.25 r180 top
D4 "ESDLC3V3D3B" SOD-323 21.5,-38.5 r180 top
D5 "ESDLC3V3D3B" SOD-323 21.5,-42 r180 top
D6 "ESDLC3V3D3B" SOD-323 36.925,-31.5 r180 top
D7 "ESDLC3V3D3B" SOD-323 21.5,-31 r180 top
D8 "ESDLC3V3D3B" SOD-323 21.5,-32.75 r180 top
D9 "ESDLC3V3D3B" SOD-323 21.5,-35 r180 top
D10 "ESDLC3V3D3B" SOD-323 21.5,-36.75 r180 top
D11 "ESDLC3V3D3B" SOD-323 36.925,-28 r180 top
D12 "ESDLC3V3D3B" SOD-323 36.925,-29.75 r180 top
D13 "ESD15VAPB" SOT23-3 21.844,-86.614 r90 bottom
D14 "ESD5B5.0ST1G" SOD-523 21.5,-53.5 r180 top
D15 "ESD5B5.0ST1G" SOD-523 21.5,-67.5 r180 top
D16 "ESDLC3V3D3B" SOD-323 128.25,-65.75 r180 top
D17 "ESDSM712" SOT23-3 33.737,-45.912 r0 bottom
D18 "ESD5V0D3B" SOD-323 40,-52.75 r0 top
D19 "SMBJ24CA" DO-214AA 128.25,-37.25 r180 top
D20 "ESDLC3V3D3B" SOD-323 22,-125.5 r180 top
D21 "ESDLC3V3D3B" SOD-323 22,-121.5 r180 top
D22 "ESDLC3V3D3B" SOD-323 22,-127.5 r180 top
D23 "ESDLC3V3D3B" SOD-323 34.106,1.11 r90 top
D24 "ESDLC3V3D3B" SOD-323 34.106,7.442 r270 top
D25 "ESDLC3V3D3B" SOD-323 34.106,-21.445 r90 top
D26 "ESDLC3V3D3B" SOD-323 34.106,-15.11 r270 top
D27 "ESDLC3V3D3B" SOD-323 131.953,-129.032 r270 top
D28 "ESDLC3V3D3B" SOD-323 129.54,-140.462 r0 bottom
D29 "ESDLC3V3D3B" SOD-323 129.54,-138.43 r0 bottom
D30 "ESDLC3V3D3B" SOD-323 129.54,-140.462 r0 top
D31 "ESDLC3V3D3B" SOD-323 129.54,-138.43 r0 top
D32 "ESDLC3V3D3B" SOD-323 129.54,-136.398 r0 top
D33 "ESDLC3V3D3B" SOD-323 129.54,-134.366 r0 top
D34 "SMBJ24CA" DO-214AA 128.25,-28.75 r180 top
D35 "ESDLC3V3D3B" SOD-323 40.25,-79.25 r0 bottom
D36 "ESDLC3V3D3B" SOD-323 40.25,-76.25 r0 bottom
D37 "ESDLC3V3D3B" SOD-323 40.25,-73.25 r0 bottom
D38 "ESDLC3V3D3B" SOD-323 20.25,-70.5 r180 top
D39 "ESDLC3V3D3B" SOD-323 20.25,-74.5 r180 top
D40 "ESDLC3V3D3B" SOD-323 20.25,-72.5 r180 top
D41 "ESDLC3V3D3B" SOD-323 22,-129.5 r180 top
D42 "ESD5V0D3B" SOD-323 20.5,-133.75 r180 top
D43 "ESDLC3V3D3B" SOD-323 21.5,-43.75 r180 top
D44 "ESDLC3V3D3B" SOD-323 21.5,-47.5 r180 top
D45 "ESDLC3V3D3B" SOD-323 21.5,-45.5 r180 top
D46 "SMBJ24CA" DO-214AA 20.5,-140.75 r0 top
D47 "ESDLC3V3D3B" SOD-323 21.5,-40.25 r180 top
D48 "SMBJ24CA" DO-214AA 20.5,-114.5 r0 top
D49 "SMBJ24CA" DO-214AA 20.5,-99.75 r0 top
D50 "SMBJ24CA" DO-214AA 20.5,-149.25 r0 top
D51 "SMBJ24CA" DO-214AA 20.5,-106.75 r0 top
D52 "B0540WS" SOD-323 40.007,-60.25 r0 top
D53 "BAT54CW" SOT-323 102.65,-96.15 r90 top
D54 "ESD5V0D3B" SOD-323 34.25,-148.35 r90 top
D55 "ESD5V0D3B" SOD-323 121,-52.96 r90 top
D56 "ESDLC3V3D3B" SOD-323 22,-119.5 r180 top
D57 "ESDLC3V3D3B" SOD-323 22,-123.5 r180 top
D58 "ESDLC3V3D3B" SOD-323 22,-117.5 r180 top
D59 "SMBJ24CA" DO-214AA 20.5,-133.75 r0 top
D60 "SS36" DO-214AC 106.25,-122.25 r270 top
D61 "SS36" DO-214AC 106.25,-113.87 r270 top
D62 "B0540WS" SOD-323 37.25,-54 r270 top
D63 "B0540WS" SOD-323 40.007,-55.25 r0 top
D64 "SS36" DO-214AC 132,7.5 r180 top
D65 "ESD5V0D3B" SOD-323 128.25,-33 r0 top
D66 "SMBJ24CA" DO-214AA 128.25,-45.75 r180 top
D67 "SMBJ24CA" DO-214AA 128.215,-41.535 r180 top
D68 "ESDLC3V3D3B" SOD-323 128.25,-37.25 r0 top
D69 "ESDLC3V3D3B" SOD-323 128.25,-28.75 r0 top
D70 "SMBJ24CA" DO-214AA 128.25,-33 r180 top
D71 "ESDLC3V3D3B" SOD-323 128.25,-74.75 r180 top
D72 "ESDLC3V3D3B" SOD-323 128.25,-71.75 r180 top
D73 "ESDLC3V3D3B" SOD-323 128.25,-68.75 r180 top
D74 "ESDLC3V3D3B" SOD-323 129.1,-58.75 r90 top
F1 "SMD020-1206" R1206 23.216,-81.585 r270 top
F2 "SMD020-1206" R1206 20.447,-81.585 r270 top
FB1 "FB_0805" L0805 57.531,-0.635 r270 top
FB2 "FB_0805" L0805 26,-129.5 r0 top
FB3 "FB_0805" L0805 34.25,-135.25 r90 top
FB4 "FB_0603" L0603 119,-80 r180 top
FB5 "FB_0603" L0603 91.25,-96 r90 bottom
FB6 "FB_0805" L0805 57.386,-22.86 r270 top
FB7 "FB_0603" L0603 41.362,-92.837 r270 top
FB8 "FB_0805" L0805 40.925,-31.5 r0 top
FB9 "FB_0603" L0603 23.75,-72.5 r180 top
FB10 "FB_0805" L0805 106.5,-54.25 r180 top
FB11 "FB_0805" L0805 34.25,-140.25 r90 top
FB12 "FB_1206" L1206 85.11,-10.541 r0 top
FB13 "FB_0603" L0603 64.182,-199.746 r0 bottom
FB14 "FB_0603" L0603 61.342,-190.515 r90 top
FB15 "FB_0603" L0603 70.644,-187.646 r0 bottom
FB16 "FB_0603" L0603 23.75,-70.5 r180 top
FB17 "FB_0603" L0603 23.75,-74.5 r180 top
FB18 "FB_0805" L0805 40.925,-28 r0 top
FB19 "FB_0805" L0805 40.925,-29.75 r0 top
FB20 "FB_0603" L0603 129.54,-131.318 r0 top
FB21 "FB_0805" L0805 34.225,-112.355 r270 top
FB22 "FB_0805" L0805 34.25,-104.1 r90 top
FB23 "FB_0805" L0805 34.225,-143.75 r270 top
FB24 "FB_0805" L0805 34.25,-109 r90 top
FB26 "FB_0603" L0603 64.322,-172.296 r0 bottom
FB27 "FB_0603" L0603 61.482,-163.065 r90 top
FB28 "FB_0603" L0603 70.784,-160.196 r0 bottom
FB29 "FB_0603" L0603 123.77,-107.21 r270 top
FB30 "FB_0603" L0603 123.77,-101.96 r270 top
FB31 "FB_0603" L0603 123.75,-96.75 r270 top
FB32 "FB_0603" L0603 123.77,-91.46 r270 top
FB33 "FB_0805" L0805 47.35,-148 r0 top
FB34 "FB_0603" L0603 21.5,-54.75 r180 top
FB35 "FB_0603" L0603 21.5,-66.25 r180 top
FB36 "FB_0603" L0603 128.25,-64 r0 top
FB1007 "FB_0603" L0603 119.9,-40.5 r0 top
FV1 "SMD1812-230C" D1812 22.086,13.404 r0 top
FV2 "SMD1812-230C" D1812 23.75,-6.75 r270 top
J1 "单排排母8p" SIP8TM-2R54 121.641,-173.505 r90 top
J2 "DB9_弯针母头" DB9TM-RF#1 136.139,-130.223 r90 top
J3 "双胞胎DB9_弯针母头" DB9TM-RF-双胞胎#1 8.626,-68.157 r270 top
J4 "DB9_弯针母头" DB9TM-RF#1 136.139,-96.423 r90 top
J5 "双胞胎DB9_弯针母头" DB9TM-RF-双胞胎#2 8.626,-34.351 r270 top
J6 "双胞胎DB9_弯针母头" DB9TM-RF-双胞胎#1 8.626,-101.963 r270 top
J7 "DB2" DB2TM-VM 134.485,-2.651 r270 top
J8 "双胞胎DB9_弯针母头" DB9TM-RF-双胞胎#2 8.626,-135.769 r270 top
J9 "DB9_弯针母头" DB9TM-RF#2 136.139,-28.811 r90 top
J10 "RJ45插座" RJ45TH-1x1-2R54-LED#1 128.57,-183.34 r90 top
J11 "单排排母8p" SIP8TM-2R54 121.641,-194.66 r90 top
J12 "DB9_弯针母头" DB9TM-RF#2 136.16,-62.617 r90 top
L1 "FB_0805" L0805 45.494,-88.31 r270 top
L2 "FB_0805" L0805 95,-161 r180 top
L11 "100uH" PL2SM-12R5x12R5 86.487,10.287 r270 top
L12 "FB_0805" L0805 102.9,-74.5 r0 top
Q1 "MMBT2222" SOT23-3 102.37,-112.54 r270 top
Q2 "MMBT2222" SOT23-3 108.75,-145.75 r180 top
Q3 "MMBT2222" SOT23-3 116.02,-107.21 r180 top
Q4 "MMBT2222" SOT23-3 102.35,-120.9 r270 top
Q5 "MMBT2222" SOT23-3 116,-102 r180 top
Q6 "MMBT2222" SOT23-3 108.75,-136 r180 top
Q7 "MMBT2222" SOT23-3 108.75,-142.5 r180 top
Q8 "MMBT2222" SOT23-3 108.75,-132.75 r180 top
Q9 "MMBT2222" SOT23-3 31,-96 r0 top
Q10 "MMBT2222" SOT23-3 116,-96.75 r180 top
Q11 "MMBT2222" SOT23-3 116.02,-91.46 r180 top
Q12 "MMBT2222" SOT23-3 108.75,-139.25 r180 top
Q13 "MMBT2222" SOT23-3 108.75,-129.5 r180 top
Q14 "MMBT2222" SOT23-3 47.244,-112.395 r0 top
Q15 "MMBT2222" SOT23-3 47.25,-143.25 r0 top
R1 "4.7K" R0603 94.75,-81.75 r0 bottom
R2 "4.7K" R0603 85.5,-119 r90 top
R3 "4.7K" R0603 84.25,-119 r90 top
R4 "4.7K" R0603 118.923,-172.134 r270 top
R5 "4.7K" R0603 118.923,-168.8 r90 top
R6 "4.7K" R0603 118.923,-165.466 r270 top
R7 "4.7K" R0603 118.923,-158.152 r270 top
R8 "1K" R0603 118.923,-162.132 r270 top
R9 "0Ω" R0603 23,-88.25 r90 top
R10 "1K" R0603 88.75,-93.25 r0 bottom
R11 "30Ω" R0603 90.75,-114.5 r270 top
R12 "30Ω" R0603 89.25,-114.5 r270 top
R13 "30Ω" R0603 40.25,-70.5 r180 top
R14 "30Ω" R0603 40.25,-69.25 r180 top
R15 "4.7K" R0603 119.25,-52.96 r270 top
R16 "180Ω" R0603 107.442,-51.689 r0 top
R17 "4.7K" R0603 40.25,-71.75 r180 top
R18 "4.7K" R0603 40.25,-80.75 r180 top
R19 "30Ω" R0603 25.5,-27.5 r0 top
R20 "30Ω" R0603 79.25,-119 r90 top
R21 "1K" R0603 88,-74.75 r180 bottom
R22 "300Ω" R0603 38.871,-92.837 r90 top
R23 "30Ω" R0603 25.5,-29.25 r0 top
R24 "30Ω" R0603 26,-121.5 r180 top
R25 "30Ω" R0603 25.5,-43 r0 top
R26 "30Ω" R0603 78,-119 r90 top
R27 "30Ω" R0603 76.75,-119 r90 top
R28 "1K" R0603 99.75,-114.65 r270 top
R29 "30Ω" R0603 76,-57.5 r90 top
R30 "30Ω" R0603 77.25,-57.5 r90 top
R31 "180Ω" R0603 113.284,-143.51 r270 bottom
R32 "30Ω" R0603 78.5,-57.5 r90 top
R33 "4.7K" R0603 36.606,-47.493 r270 top
R34 "4.7K" R0603 113.284,-140.462 r90 bottom
R35 "30Ω" R0603 79.75,-57.5 r90 top
R36 "30Ω" R0603 48.882,-49.75 r180 top
R37 "180Ω" R0603 124.079,-129.286 r90 top
R38 "4.7K" R0603 121.251,-132.5 r0 bottom
R39 "1K" R0603 104.75,-145.75 r90 top
R40 "1K" R0603 104.75,-136 r90 top
R41 "30Ω" R0603 48.882,-42.25 r180 top
R42 "30Ω" R0603 26,-117.5 r0 top
R43 "30Ω" R0603 25.5,-46 r0 top
R44 "4.7K" R0603 36.606,-44.369 r270 top
R45 "30Ω" R0603 103,-82.75 r180 top
R46 "360Ω" R0603 30.25,-131.75 r0 top
R47 "30Ω" R0603 75.5,-119 r90 top
R48 "30Ω" R0603 67.184,-184.419 r90 top
R49 "100Ω" R0603 23.495,-76.302 r180 top
R50 "360Ω" R1206 28.75,-136.5 r180 top
R51 "4.7K" R0603 110.25,-68.35 r270 top
R52 "100Ω" R0603 23.495,-77.724 r180 top
R53 "0Ω" R0603 22.25,-90.5 r0 top
R54 "1K" R0603 102.25,-115.75 r180 top
R55 "open" R0603 21.5,-88.25 r270 top
R56 "30Ω" R0603 119.85,-36.75 r180 top
R57 "0Ω" R0603 20.5,-136.5 r180 top
R58 "4.7K" R0603 34.25,-151.4 r90 top
R59 "30Ω" R0603 74.25,-119 r90 top
R60 "30Ω" R0603 68.454,-184.419 r90 top
R61 "0Ω" R0603 34.854,1.092 r180 bottom
R62 "49.9Ω" R0603 34.925,8.693 r0 bottom
R63 "82Ω" R0603 34.854,2.381 r180 bottom
R64 "49.9Ω" R0603 34.925,6.153 r0 bottom
R65 "82Ω" R0603 34.854,-0.197 r180 bottom
R66 "10Ω" R0603 34.925,7.423 r0 bottom
R67 "4.7K" R0603 55.01,11.552 r90 top
R68 "30Ω" R0603 41.027,2.368 r180 top
R69 "4.7K" R0603 59.142,6.731 r270 top
R70 "30Ω" R0603 41.027,3.562 r180 top
R71 "30Ω" R0603 41.027,4.756 r180 top
R72 "30Ω" R0603 41.027,5.95 r180 top
R73 "300Ω" R0603 56.692,-5.745 r90 top
R74 "75Ω" R0805 20.828,7.319 r180 bottom
R75 "1M" R0603 59.142,2.649 r270 top
R76 "75Ω" R0805 20.828,5.506 r180 bottom
R77 "4.7K" R0603 45.612,11.552 r90 top
R78 "300Ω" R0603 54.266,-5.745 r90 top
R79 "75Ω" R1206 28.69,12.769 r180 top
R80 "12.4K" R0603 41.027,1 r0 top
R81 "4.7K" R0603 46.786,11.552 r90 top
R82 "4.7K" R0603 47.961,11.552 r90 top
R83 "1K" R0603 51.84,-5.745 r90 top
R84 "1K" R0603 53.835,11.552 r270 top
R85 "1K" R0603 52.66,11.552 r270 top
R86 "1K" R0603 51.485,11.552 r270 top
R87 "1K" R0603 50.311,11.552 r270 top
R88 "1K" R0603 49.136,11.552 r270 top
R89 "4.7K" R0603 112.75,-68.35 r270 top
R90 "30Ω" R0603 120.5,-28.75 r180 top
R91 "30Ω" R0603 119,-73.75 r180 top
R92 "30Ω" R0603 119,-72.5 r0 top
R93 "30Ω" R0603 119,-75 r0 top
R94 "30Ω" R0603 73,-119 r90 top
R95 "30Ω" R0603 71.75,-119 r90 top
R96 "30Ω" R0603 110,-47 r180 top
R97 "30Ω" R0603 106.65,-47 r180 top
R98 "30Ω" R0603 70.5,-119 r90 top
R99 "30Ω" R0603 69.724,-184.419 r90 top
R100 "30Ω" R0603 69.25,-119 r90 top
R101 "2K 1%" R0603 95.25,1.75 r0 top
R102 "6.2K 1%" R0603 91.5,1 r90 top
R103 "open" R0603 21.5,-92.75 r90 top
R104 "0Ω" R0603 28,-96 r270 top
R105 "180Ω" R0603 46.5,-150.6 r270 top
R106 "30Ω" R0603 109.75,-102 r270 top
R107 "30Ω" R0603 128.25,-73.25 r0 top
R108 "6.2K 1%" R0603 130,-21.75 r270 top
R109 "4.7K" R0603 131.25,-18.65 r270 top
R110 "2K 1%" R0603 127.5,-21.75 r90 top
R111 "30Ω" R0603 68,-119 r90 top
R112 "30Ω" R0603 70.994,-184.419 r90 top
R113 "30Ω" R0603 66.75,-119 r90 top
R114 "30Ω" R0603 72.264,-184.419 r90 top
R115 "30Ω" R0603 60.5,-119 r270 top
R116 "30Ω" R0603 25.5,-38.5 r0 top
R117 "30Ω" R0603 73.576,-184.429 r90 top
R118 "30Ω" R0603 77.905,-189.682 r0 top
R119 "30Ω" R0603 65.5,-119 r90 top
R120 "4.7K" R0603 40.25,-74.75 r180 top
R121 "4.7K" R0603 40.25,-77.75 r180 top
R122 "30Ω" R0603 77.905,-190.952 r0 top
R123 "30Ω" R0603 61.75,-119 r270 top
R124 "30Ω" R0603 77.905,-192.222 r0 top
R125 "30Ω" R0603 77.905,-193.492 r0 top
R126 "30Ω" R0603 77.905,-194.762 r0 top
R127 "30Ω" R0603 40.25,-79.25 r180 top
R128 "30Ω" R0603 40.25,-76.25 r180 top
R129 "30Ω" R0603 40.25,-73.25 r180 top
R130 "30Ω" R0603 77.905,-196.032 r0 top
R131 "30Ω" R0603 77.905,-197.302 r0 top
R132 "30Ω" R0603 77.905,-198.572 r0 top
R133 "30Ω" R0603 64.517,-202.453 r90 top
R134 "30Ω" R0603 65.787,-202.453 r90 top
R135 "30Ω" R0603 67.057,-202.453 r90 top
R136 "30Ω" R0603 68.327,-202.453 r90 top
R137 "30Ω" R0603 69.597,-202.453 r90 top
R138 "30Ω" R0603 70.867,-202.453 r90 top
R139 "30Ω" R0603 72.137,-202.453 r90 top
R140 "30Ω" R0603 73.407,-202.453 r90 top
R141 "30Ω" R0603 64.25,-119 r90 top
R142 "30Ω" R0603 63,-119 r90 top
R143 "4.7K" R0603 98.5,-172.5 r90 top
R144 "open" R0603 23,-92.75 r90 top
R145 "10K" R0603 113,-180.25 r180 top
R146 "0Ω" R0603 25.5,-96 r90 top
R147 "4.7K" R0603 119,-193.75 r270 top
R148 "4.7K" R0603 119,-190 r90 top
R149 "100K 1%" R0603 21.5,-57.25 r180 top
R150 "100Ω" R0603 21.5,-60 r0 top
R151 "30Ω" R0603 32,-55.5 r0 top
R152 "30Ω" R0603 121.246,-131.191 r0 bottom
R153 "4.7K" R0603 128.651,-129.071 r270 top
R154 "200K 1%" R0603 21.5,-58.75 r180 top
R155 "4.7K" R0603 119,-186.5 r270 top
R156 "4.7K" R0603 119,-178.5 r90 top
R157 "1K" R0603 119,-183 r270 top
R158 "open" R0603 25.5,-55.5 r0 top
R159 "6.2K 1%" R0603 117.75,-21.75 r270 top
R160 "4.7K" R0603 119.25,-18.5 r0 top
R161 "0Ω" R0603 28.75,-55.5 r0 top
R162 "300Ω" R0603 55.596,-28.161 r90 top
R163 "2K 1%" R0603 116.5,-21.75 r90 top
R164 "1K" R0603 89.5,-182.25 r0 top
R165 "300Ω" R0603 55.479,-5.745 r270 top
R166 "681" R0603 93,1 r270 top
R167 "30Ω" R0603 25.5,-41.5 r0 top
R168 "30Ω" R0603 25.5,-31 r0 top
R169 "30Ω" R0603 25.5,-32.75 r0 top
R170 "30Ω" R0603 25.5,-35 r0 top
R171 "30Ω" R0603 25.5,-36.75 r0 top
R172 "4.7K" R0603 85.75,-114.5 r270 top
R173 "30Ω" R0603 109.75,-107.25 r270 top
R174 "30Ω" R0603 128.25,-70.25 r0 top
R175 "30Ω" R0603 128.25,-67.25 r0 top
R176 "30Ω" R0603 131.25,-21.75 r90 top
R177 "30Ω" R0603 40.25,-68 r0 top
R178 "30Ω" R0603 40.25,-66.75 r0 top
R179 "43K 1%" R0603 91.25,-57.5 r270 top
R180 "1K" R0603 91.288,-63.884 r90 top
R181 "6.2K 1%" R0603 92.25,-60 r180 top
R182 "0Ω" R0603 20.5,-137.75 r180 top
R183 "3K" R1206 28.75,-140.75 r0 top
R184 "3K" R1206 28.75,-143.5 r180 top
R185 "0Ω" R0603 20.5,-143.5 r180 top
R186 "open" R0603 35.082,-46.032 r90 top
R187 "0Ω" R0603 20.5,-144.75 r180 top
R188 "180Ω" R0603 47.5,-115 r180 top
R189 "3K" R1206 28.75,-114.5 r0 top
R190 "1K" R0603 50.25,-115.85 r90 top
R191 "3K" R1206 28.75,-99.75 r0 top
R192 "180Ω" R0603 47.4,-145.75 r180 top
R193 "3K" R1206 28.75,-149.25 r0 top
R194 "3K" R1206 28.75,-102.5 r180 top
R195 "1K" R0603 102.35,-123.94 r180 top
R196 "1K" R0603 99.5,-123 r270 top
R197 "1K" R0603 50.25,-146.5 r90 top
R198 "0Ω" R0603 20.75,-102.5 r180 top
R199 "0Ω" R0603 20.75,-103.75 r180 top
R200 "open" R0603 47.5,-116.75 r180 top
R201 "3K" R1206 28.75,-106.75 r0 top
R202 "0Ω" R0603 47.5,-118.25 r180 top
R203 "0Ω" R0603 47.498,-119.634 r180 top
R204 "3K" R1206 28.75,-109.5 r180 top
R205 "0Ω" R0603 47.35,-128.56 r0 top
R206 "0Ω" R0603 20.5,-109.5 r180 top
R207 "0Ω" R0603 20.5,-110.75 r180 top
R208 "30Ω" R0603 109.75,-91.5 r270 top
R209 "30Ω" R0603 86.5,-111.25 r180 top
R210 "0Ω" R0603 48.882,-43.5 r180 top
R211 "0Ω" R0603 62.75,-57.5 r90 top
R212 "0Ω" R0603 64,-57.5 r90 top
R213 "30Ω" R0603 26,-119.5 r0 top
R214 "30Ω" R0603 25.5,-44.5 r0 top
R215 "30Ω" R0603 25.5,-40 r0 top
R216 "open" R0603 101.75,-97.75 r180 top
R217 "4.7K" R0603 46.5,-135.6 r90 top
R218 "4.7K" R0603 47.35,-139.8 r180 top
R219 "4.7K" R0603 46.5,-104.1 r90 top
R220 "4.7K" R0603 46.4,-109.1 r90 top
R221 "30Ω" R0603 59.182,-118.999 r270 top
R222 "30Ω" R0603 57.912,-118.999 r270 top
R223 "30Ω" R0603 109.75,-96.75 r270 top
R224 "0Ω" R0603 22.25,-95 r0 top
R225 "1K" R0603 34.25,-96 r270 top
R226 "1K" R0603 36.25,-96 r270 top
R227 "3K" R1206 28.75,-133.75 r0 top
R228 "4.7K" R0603 47.5,-122.25 r0 top
R229 "30Ω" R0603 26,-127.5 r0 top
R230 "30Ω" R0603 26,-125.5 r0 top
R231 "30Ω" R0603 26,-123.5 r0 top
R232 "30Ω" R0603 67.324,-156.969 r90 top
R233 "30Ω" R0603 68.594,-156.969 r90 top
R234 "30Ω" R0603 69.864,-156.969 r90 top
R235 "30Ω" R0603 71.134,-156.969 r90 top
R236 "30Ω" R0603 72.404,-156.969 r90 top
R237 "30Ω" R0603 73.716,-156.979 r90 top
R238 "30Ω" R0603 78.045,-162.232 r0 top
R239 "30Ω" R0603 78.045,-163.502 r0 top
R240 "30Ω" R0603 78.045,-164.772 r0 top
R241 "30Ω" R0603 78.045,-166.042 r0 top
R242 "30Ω" R0603 78.045,-167.312 r0 top
R243 "30Ω" R0603 78.045,-168.582 r0 top
R244 "30Ω" R0603 78.045,-169.852 r0 top
R245 "30Ω" R0603 78.045,-171.122 r0 top
R246 "30Ω" R0603 64.657,-175.003 r90 top
R247 "30Ω" R0603 65.927,-175.003 r90 top
R248 "30Ω" R0603 67.197,-175.003 r90 top
R249 "30Ω" R0603 68.467,-175.003 r90 top
R250 "30Ω" R0603 69.737,-175.003 r90 top
R251 "30Ω" R0603 71.007,-175.003 r90 top
R252 "30Ω" R0603 72.277,-175.003 r90 top
R253 "30Ω" R0603 73.547,-175.003 r90 top
R254 "10K" R0603 122.27,-107.21 r90 top
R255 "10K" R0603 122.27,-101.96 r90 top
R256 "1K" R0603 120.77,-107.21 r90 top
R257 "1K" R0603 120.77,-101.96 r90 top
R258 "10K" R0603 119.27,-107.21 r270 top
R259 "10K" R0603 119.27,-101.96 r270 top
R260 "1K" R0603 111.25,-107.25 r90 top
R261 "1K" R0603 111.25,-102 r90 top
R262 "1K" R0603 112.75,-107.25 r270 top
R263 "0Ω" R0603 34.854,-21.435 r180 bottom
R264 "49.9Ω" R0603 34.995,-13.825 r0 bottom
R265 "82Ω" R0603 34.854,-20.175 r180 bottom
R266 "49.9Ω" R0603 34.995,-16.381 r0 bottom
R267 "82Ω" R0603 34.854,-22.695 r180 bottom
R268 "10Ω" R0603 34.995,-15.103 r0 bottom
R269 "4.7K" R0603 55.01,-10.635 r90 top
R270 "30Ω" R0603 40.981,-19.797 r180 top
R271 "4.7K" R0603 59.142,-15.367 r270 top
R272 "30Ω" R0603 40.981,-18.606 r180 top
R273 "30Ω" R0603 40.981,-17.415 r180 top
R274 "30Ω" R0603 40.981,-16.223 r180 top
R275 "300Ω" R0603 56.802,-28.161 r90 top
R276 "75Ω" R0805 19.328,-10.275 r180 bottom
R277 "1M" R0603 59.142,-19.66 r270 top
R278 "75Ω" R0805 19.328,-12.053 r180 bottom
R279 "4.7K" R0603 45.612,-10.635 r90 top
R280 "300Ω" R0603 54.391,-28.161 r90 top
R281 "75Ω" R1206 29.25,-9 r180 top
R282 "12.4K" R0603 41,-21 r0 top
R283 "4.7K" R0603 46.786,-10.635 r90 top
R284 "4.7K" R0603 47.961,-10.635 r90 top
R285 "1K" R0603 51.918,-28.161 r90 top
R286 "1K" R0603 53.835,-10.635 r270 top
R287 "1K" R0603 52.66,-10.635 r270 top
R288 "1K" R0603 51.485,-10.635 r270 top
R289 "1K" R0603 50.311,-10.635 r270 top
R290 "1K" R0603 49.136,-10.635 r270 top
R291 "1K" R0603 112.75,-102 r270 top
R292 "10K" R0603 122.25,-96.75 r90 top
R293 "10K" R0603 122.27,-91.46 r90 top
R294 "1K" R0603 120.75,-96.75 r90 top
R295 "1K" R0603 120.77,-91.46 r90 top
R296 "10K" R0603 119.25,-96.75 r270 top
R297 "10K" R0603 119.27,-91.46 r270 top
R298 "1K" R0603 111.25,-96.75 r90 top
R299 "1K" R0603 111.27,-91.46 r90 top
R300 "1K" R0603 112.75,-96.75 r270 top
R301 "1K" R0603 112.77,-91.46 r270 top
R302 "30Ω" R0603 107.25,-31.75 r270 top
R303 "open" R0603 56.607,-60.5 r0 top
R304 "4.7K" R0603 40.007,-57 r180 top
R305 "open" R0603 59.007,-57.6 r90 top
R306 "100K 1%" R0603 21.5,-63.75 r180 top
R307 "100Ω" R0603 21.5,-61.25 r0 top
R308 "3K" R1206 121.75,-33 r0 top
R309 "30Ω" R0603 56.007,-118.999 r270 top
R310 "30Ω" R0603 54.5,-102.75 r180 top
R311 "30Ω" R0603 54.5,-101.5 r180 top
R312 "30Ω" R0603 54.5,-100.25 r180 top
R313 "0Ω" R0603 19,-92.75 r90 top
R314 "open" R0603 20.25,-92.75 r90 top
R315 "1K" R0603 106,-145.75 r90 top
R316 "1K" R0603 106,-136 r90 top
R317 "4.7K" R0603 108.75,-31.75 r90 top
R318 "30Ω" R0603 29.5,-65.75 r0 top
R319 "200K 1%" R0603 21.5,-62.5 r180 top
R320 "open" R0603 26.4,-67 r180 top
R321 "0Ω" R0603 26.4,-65.75 r0 top
R322 "30Ω" R0603 128.25,-61 r180 top
R323 "4.7K" R0603 104.267,-51.689 r0 top
R324 "4.7K" R0603 48.25,-150.6 r90 top
R325 "4.7K" R0603 128.25,-62.5 r0 top
R326 "30Ω" R0603 71.25,-57.5 r270 top
R327 "30Ω" R0603 72.5,-57.5 r270 top
R328 "30Ω" R0603 70,-57.5 r270 top
R329 "30Ω" R0603 68.75,-57.5 r270 top
R330 "180Ω" R0603 115.824,-143.51 r270 bottom
R331 "4.7K" R0603 115.824,-140.462 r90 bottom
R332 "180Ω" R0603 118.364,-143.51 r270 bottom
R333 "4.7K" R0603 118.364,-140.462 r90 bottom
R334 "180Ω" R0603 117.094,-131.533 r90 bottom
R335 "4.7K" R0603 117.094,-134.62 r270 bottom
R336 "180Ω" R0603 120.904,-143.51 r270 bottom
R337 "4.7K" R0603 120.904,-140.462 r90 bottom
R338 "180Ω" R0603 114.554,-131.572 r90 bottom
R339 "4.7K" R0603 114.554,-134.62 r270 bottom
R340 "1K" R0603 104.75,-142.5 r90 top
R341 "1K" R0603 104.75,-132.75 r90 top
R342 "1K" R0603 106,-142.5 r90 top
R343 "1K" R0603 106,-132.75 r90 top
R344 "1K" R0603 104.75,-139.25 r90 top
R345 "1K" R0603 104.75,-129.5 r90 top
R346 "1K" R0603 106,-139.25 r90 top
R347 "1K" R0603 106,-129.5 r90 top
R348 "1K" R0603 50.25,-112.4 r270 top
R349 "1K" R0603 50.25,-143.25 r270 top
R350 "1K" R0603 119.9,-38 r0 top
R351 "1K" R0603 120.75,-42.75 r270 top
R352 "360Ω" R0603 119.85,-35.5 r0 top
R1026 "0Ω" R0603 107.515,-44.392 r270 top
R1032 "1K 1%" R0603 107.515,-41.217 r270 top
R1033 "2K 1%" R0603 108.785,-41.217 r90 top
R1038 "0Ω" R0603 113.25,-47 r180 top
R1039 "1K 1%" R0603 119,-46 r90 top
R1040 "2K 1%" R0603 119,-42.75 r90 top
R2001 "0Ω" R0603 49.39,-171.801 r0 top
R2002 "10KΩ 1%" R0603 40.568,-164.085 r180 top
R2003 "1K" R0603 53.496,-163.952 r180 top
R2004 "180Ω" R1206 11.584,-167.503 r180 top
R2005 "7.87KΩ 1%" R0603 39.095,-171.075 r180 top
R2006 "10KΩ 1%" R0603 40.593,-162.86 r0 top
R2007 "1K" R0603 42.478,-169.955 r180 top
R2008 "1K" R0603 51.698,-170.878 r270 top
R2009 "68Ω" R1206 7.121,-165.903 r270 top
R2010 "68Ω" R1206 16.072,-165.903 r270 top
R2011 "75Ω" R0805 18.633,-166.552 r270 top
R2012 "0Ω" R0603 38.171,-167.66 r90 top
R2013 "10KΩ 1%" R0603 39.095,-165.484 r0 top
R2014 "open" R0603 40.018,-167.66 r90 top
R2015 "4.7K" R0603 21.484,-171.072 r0 top
R2016 "2.2KΩ 1%" R0603 39.095,-169.845 r0 top
R2017 "10KΩ 1%" R0603 41.58,-166.408 r270 top
R2018 "open" R0603 54.004,-167.406 r90 top
R2019 "0Ω" R0603 52.573,-167.406 r270 top
R2020 "7.87KΩ 1%" R0603 39.069,-186.16 r180 top
R2021 "10KΩ 1%" R0603 40.542,-179.245 r0 top
R2022 "0Ω" R0603 49.559,-186.64 r0 top
R2023 "10KΩ 1%" R0603 40.542,-177.97 r0 top
R2024 "1K" R0603 42.478,-184.794 r180 top
R2025 "180Ω" R1206 11.584,-182.59 r180 top
R2026 "1K" R0603 53.496,-178.986 r180 top
R2027 "2.2KΩ 1%" R0603 39.069,-184.93 r0 top
R2028 "0Ω" R0603 38.146,-182.771 r90 top
R2029 "10KΩ 1%" R0603 39.069,-180.595 r0 top
R2030 "1K" R0603 51.845,-185.717 r270 top
R2031 "68Ω" R1206 7.121,-180.812 r270 top
R2032 "68Ω" R1206 16.072,-180.812 r270 top
R2033 "75Ω" R0805 18.633,-181.665 r270 top
R2034 "open" R0603 39.992,-182.771 r90 top
R2035 "4.7K" R0603 21.571,-186.11 r0 top
R2036 "10KΩ 1%" R0603 41.466,-181.518 r270 top
R2037 "open" R0603 54.004,-182.415 r90 top
R2038 "0Ω" R0603 52.607,-182.415 r270 top
R2039 "10KΩ 1%" R0603 40.606,-194.471 r0 top
R2040 "30Ω" R0603 49.75,-202 r0 top
R2041 "7.87KΩ 1%" R0603 39.044,-201.42 r180 top
R2042 "10KΩ 1%" R0603 40.606,-193.23 r0 top
R2043 "75Ω" R1206 11.584,-197.738 r180 top
R2044 "1K" R0603 42.452,-200.13 r180 top
R2045 "1K" R0603 53.494,-193.907 r180 top
R2046 "0Ω" R0603 38.121,-198.031 r90 top
R2047 "10KΩ 1%" R0603 39.044,-195.855 r0 top
R2048 "1K" R0603 52,-201.077 r270 top
R2049 "100Ω" R1206 7.121,-196.029 r270 top
R2050 "100Ω" R1206 16.072,-196.029 r270 top
R2051 "75Ω" R0805 18.633,-196.905 r270 top
R2052 "open" R0603 39.967,-198.031 r90 top
R2053 "2.2KΩ 1%" R0603 39.044,-200.19 r0 top
R2054 "4.7K" R0603 21.571,-201.35 r0 top
R2055 "10KΩ 1%" R0603 41.529,-196.778 r270 top
R2056 "open" R0603 53.877,-197.37 r90 top
R2057 "0Ω" R0603 52.57,-197.37 r270 top
R2058 "0Ω" R0603 47.199,-170.878 r270 top
R2059 "0Ω" R0603 47.299,-185.717 r270 top
RJ1 "RJ45插座" RJ45TH-1x1-2R54-LED#2 13.82,8.682 r270 top
RJ2 "RJ45插座" RJ45TH-1x1-2R54-LED#1 13.82,-7.519 r270 top locked
RJ3 "RJ45插座" RJ45TH-1x1-2R54-LED#1 128.554,-166.913 r90 top
SMA2001 "SMA-50KFD-4" SMA-50KFD-4 2.272,-167.459 r180 top
SMA2002 "SMA-50KFD-4" SMA-50KFD-4 2.272,-182.64 r180 top
SMA2003 "SMA-50KFD-4" SMA-50KFD-4 2.272,-197.822 r180 top
T1 "HX1188NL" SOP16-1R27-7R11X12R7 26.904,4.248 r180 top
T2 "HX1188NL" SOP16-1R27-7R11x12R7 26.904,-18.27 r180 top
TP2 "TEST" TP0R8 17.094,-94.412 r270 top
TP4 "TEST" TP0R8 104.5,-194.25 r90 top
TP5 "TEST" TP0R8 103.596,-195.404 r90 top
TP6 "TEST" TP0R8 102.75,-194.25 r90 top
TP9 "TEST" TP0R8 90,-99 r180 top
TP10 "TEST" TP0R8 91,-99.75 r180 top
TP12 "TEST" TP0R8 113,-181.5 r90 top
TP13 "TEST" TP0R8 111.75,-182 r90 top
TR1 "VPT85BB-01A" VPT85BB-01A-6SM-2R54-6R65X7R45 47.507,-57.75 r270 top
U1 "AT24C02N" SOIC8_1R27_3R9X4R9 88.79,-120.853 r90 top
U2 "STM32F103VET6" LQFP100_0R5_14x14 100.77,-183.646 r0 top locked
U3 "MAX3232CSE" SOIC16-1R27-3R9X9R9 30.937,-77.597 r90 top
U4 "G5V-1-5VDC" G5V-1-5VDC 30.605,-89.801 r0 top
U5 "SN65LBC184DR" SOIC8_1R27_3R9X4R9 41.984,-45.994 r180 top
U6 "W25Q64CVSSIG" SOIC8_1R27_5R3x5R3 111.39,-72.855 r0 top
U7 "LMV358IDT" SOIC8_1R27_3R9x4R9 26.5,-60.5 r270 top
U8 "TLP2368" SO6-1R27-4R55X3R7 40.25,-134.5 r270 top
U9 "W5500" TQFN48-0R5-7X7 49.592,2.713 r0 top
U10 "ADS8411" TQFN48-0R5-7X7 68.594,-165.859 r0 top
U11 "TLP181" TLP181 40.145,-86.352 r90 top
U12 "TLP2368" SO6-1R27-4R55X3R7 40.25,-139.5 r270 top
U13 "TLP181" TLP181 40.4,-113.075 r180 top
U14 "TLP2368" SO6-1R27-4R55X3R7 40.4,-103.075 r270 top
U15 "TLP181" TLP181 40.25,-144.5 r180 top
U16 "STM32H743ZI" LQFP144_0R5_20x20 83.801,-84.987 r180 top locked
U17 "ADS8411" TQFN48-0R5-7X7 68.454,-193.309 r0 top
U18 "TPS73801" SOT-223-6 124.75,-13.75 r0 top
U19 "DS18B20U" TSSOP8-0R65-3R0x3R0 82.924,-113.743 r270 top
U20 "LM1117S-3.3" SOT-223 82.285,-19.214 r90 top
U21 "REF3133AIDBZT" SOT23-3 95.25,-165.5 r180 top
U22 "G5NB-1A-E-DC24" G5NB-1A-E-DC24-20R4X7 119.25,-122.1 r0 top
U23 "SN74HC4075DR" SOIC14-1R27-3R9x8R65 40.25,-124.75 r0 top
U24 "LM2576HVDP-ADJ" SOIC8_1R27_3R9X4R9-1 100.858,2.075 r270 top
U25 "TLP2368" SO6-1R27-4R55X3R7 40.4,-108.075 r270 top
U26 "REF3133AIDBZT" SOT23-3 103,-79.25 r90 top
U27 "LM1117S-3.3" SOT-223 96.914,-18.746 r90 top
U28 "SN74AHC1G04DC" SC70-5-1R3x2R2 48.882,-46 r180 top
U29 "Si2369DS-T1-GE3" SOT23-3 126.426,-129.216 r90 top
U30 "Si2369DS-T1-GE3" SOT23-3 128.27,-107.21 r180 top
U31 "Si2369DS-T1-GE3" SOT23-3 128.27,-101.96 r180 top
U32 "G5NB-1A-E-DC24" G5NB-1A-E-DC24-20R4X7 119.25,-113.9 r0 top
U33 "Si2369DS-T1-GE3" SOT23-3 128.25,-96.75 r180 top
U34 "TPS73801" SOT-223-6 113.75,-13.75 r0 top
U35 "Si2369DS-T1-GE3" SOT23-3 128.27,-91.46 r180 top
U36 "ADuM1201A" SOIC8_1R27_3R9x4R9 55.882,-46 r180 top
U37 "W5500" TQFN48-0R5-7X7 49.592,-19.525 r0 top
U38 "VPS8504" SOT23-6 55.757,-57.75 r180 top
U39 "LTV-247" SOIC16-1R27-3R9x9R9 117.74,-143.35 r90 top
U40 "LTV-247" SOIC16-1R27-3R9x9R9 117.729,-131.788 r270 top
U41 "TLP2368" SO6-1R27-4R55X3R7 113.85,-52.96 r270 top
U42 "TLP2368" SO6-1R27-4R55X3R7 40.25,-149.5 r90 top
U43 "TLP2368" SO6-1R27-4R55X3R7 114,-31.75 r90 top
U1007 "LM358" SOIC8_1R27_3R9x4R9 113.814,-42.911 r0 top
U2001 "ADL5511ACPZ" QFN16_0R50_3X3 26.919,-167.769 r0 top
U2002 "AD8052ARZ" SOIC8_1R27_3R9x4R9 47.117,-166.154 r180 top
U2003 "ADL5511ACPZ" QFN16_0R50_3X3 27.007,-182.884 r0 top
U2004 "AD8052ARZ" SOIC8_1R27_3R9x4R9 47.117,-181.264 r180 top
U2005 "ADL5511ACPZ" QFN16_0R50_3X3 27.007,-198.124 r0 top
U2006 "AD8052ARZ" SOIC8_1R27_3R9x4R9 47.117,-196.524 r180 top
X1 "8M" CRY2SM-6R0x3R5 101.25,-161.976 r0 top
